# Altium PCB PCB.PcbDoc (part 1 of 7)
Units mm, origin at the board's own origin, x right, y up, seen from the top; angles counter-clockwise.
Board outline 243.2 x 142.8 mm, 4 copper layers (Top Layer, Layer 1, Layer 2, Bottom Layer), stack 0.603 mm thick; 451 components, 380 nets, 2276 pads, 1520 vias.
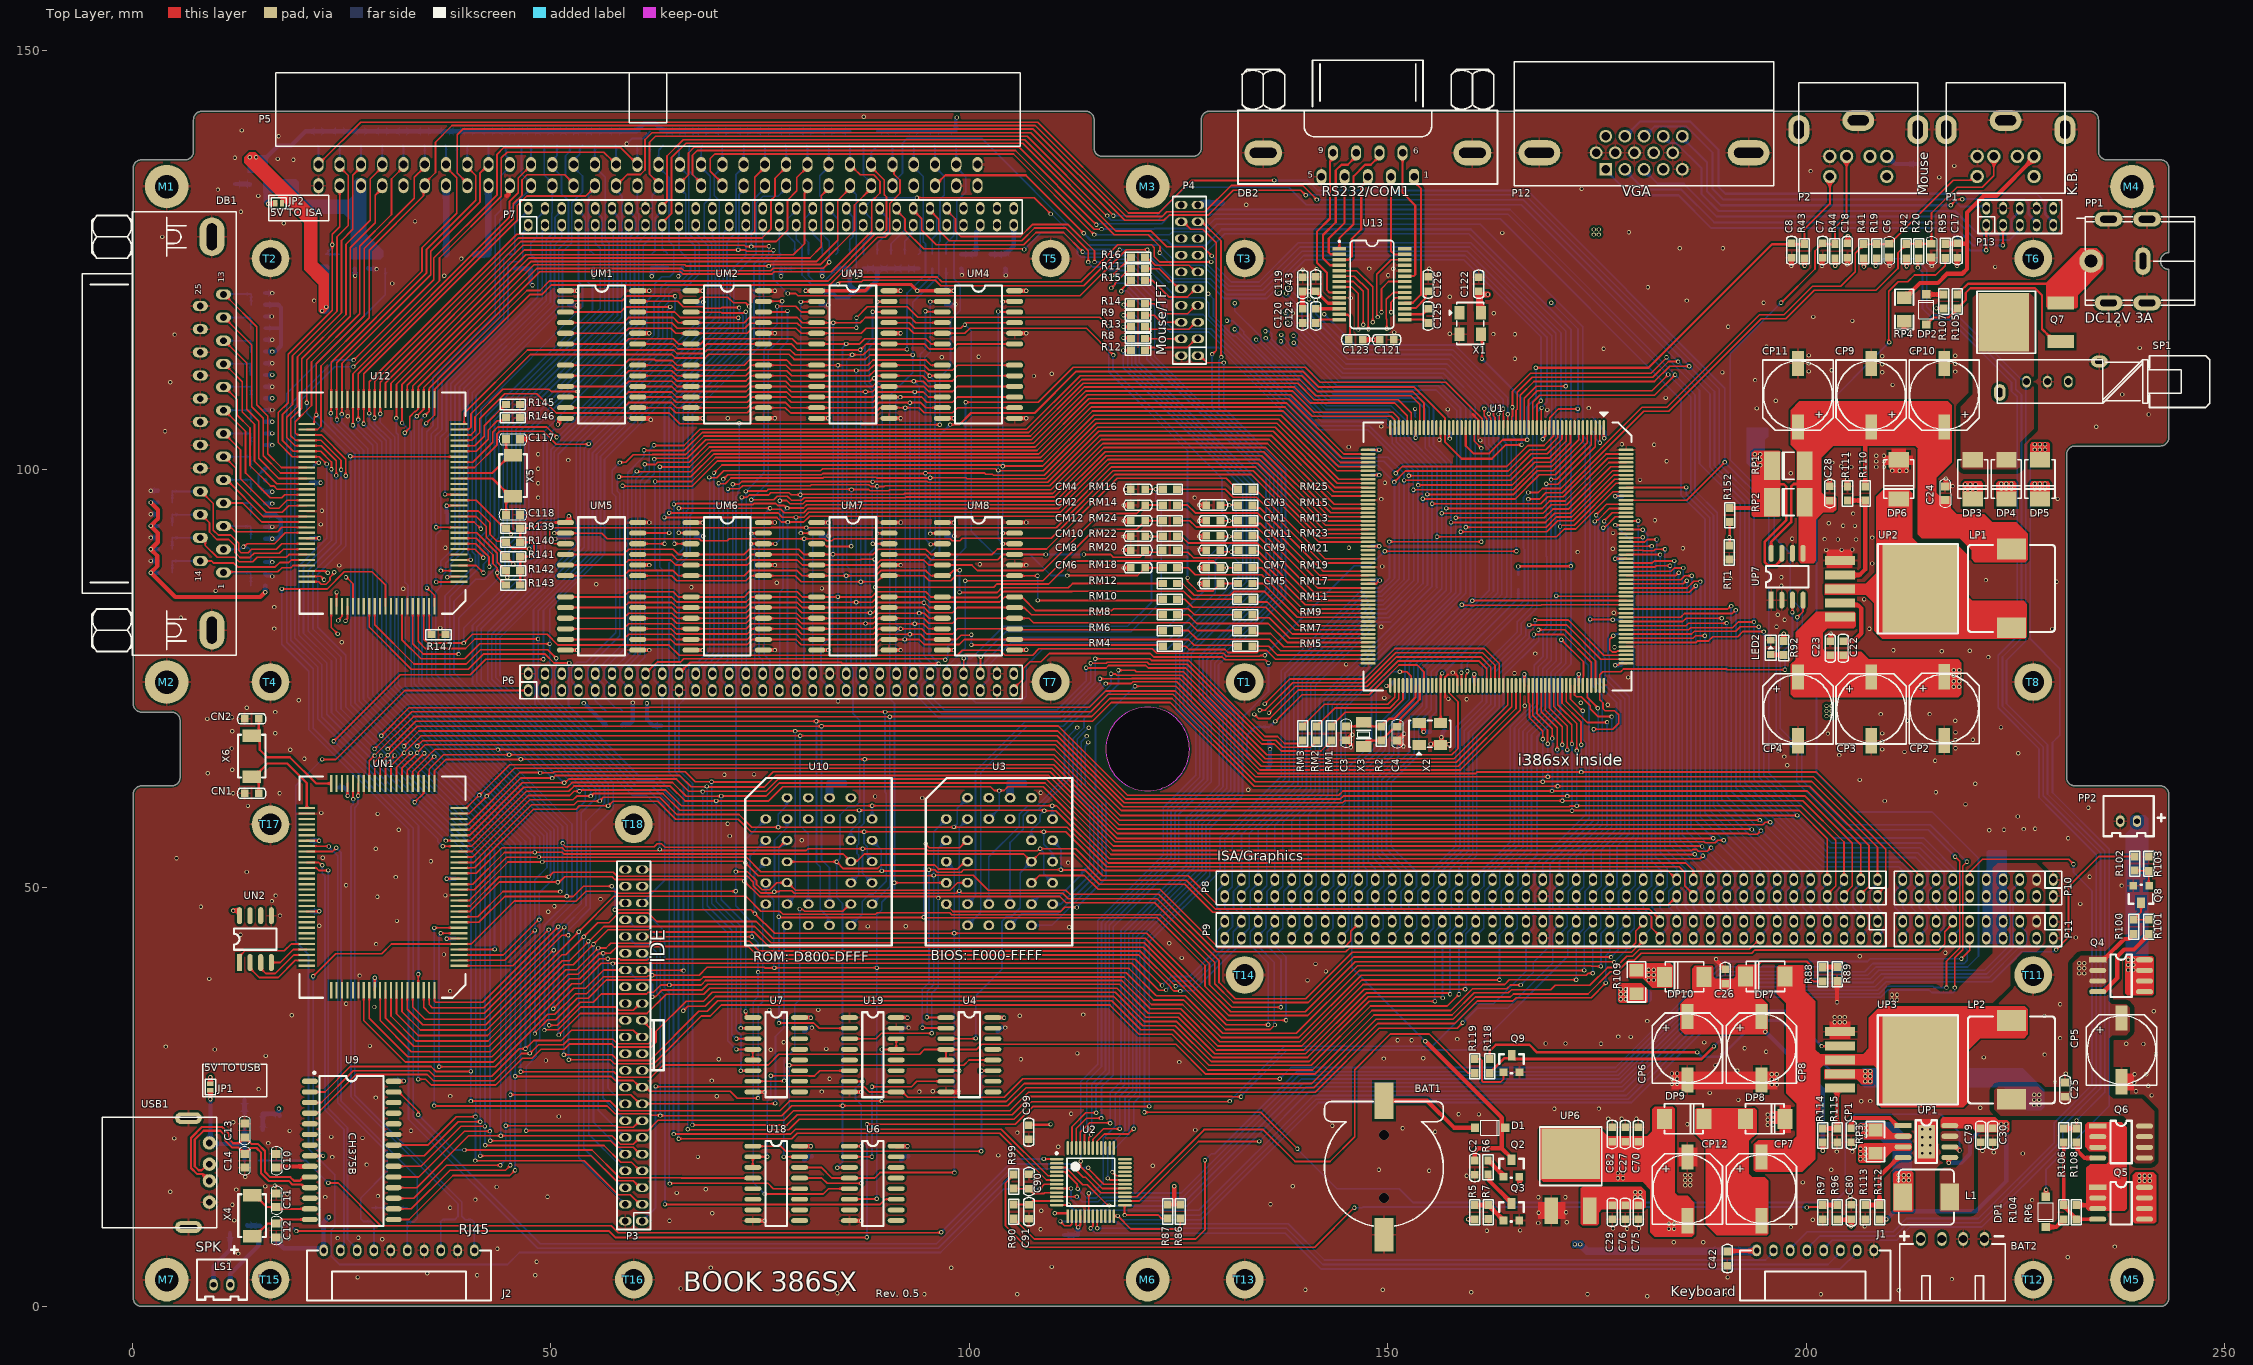
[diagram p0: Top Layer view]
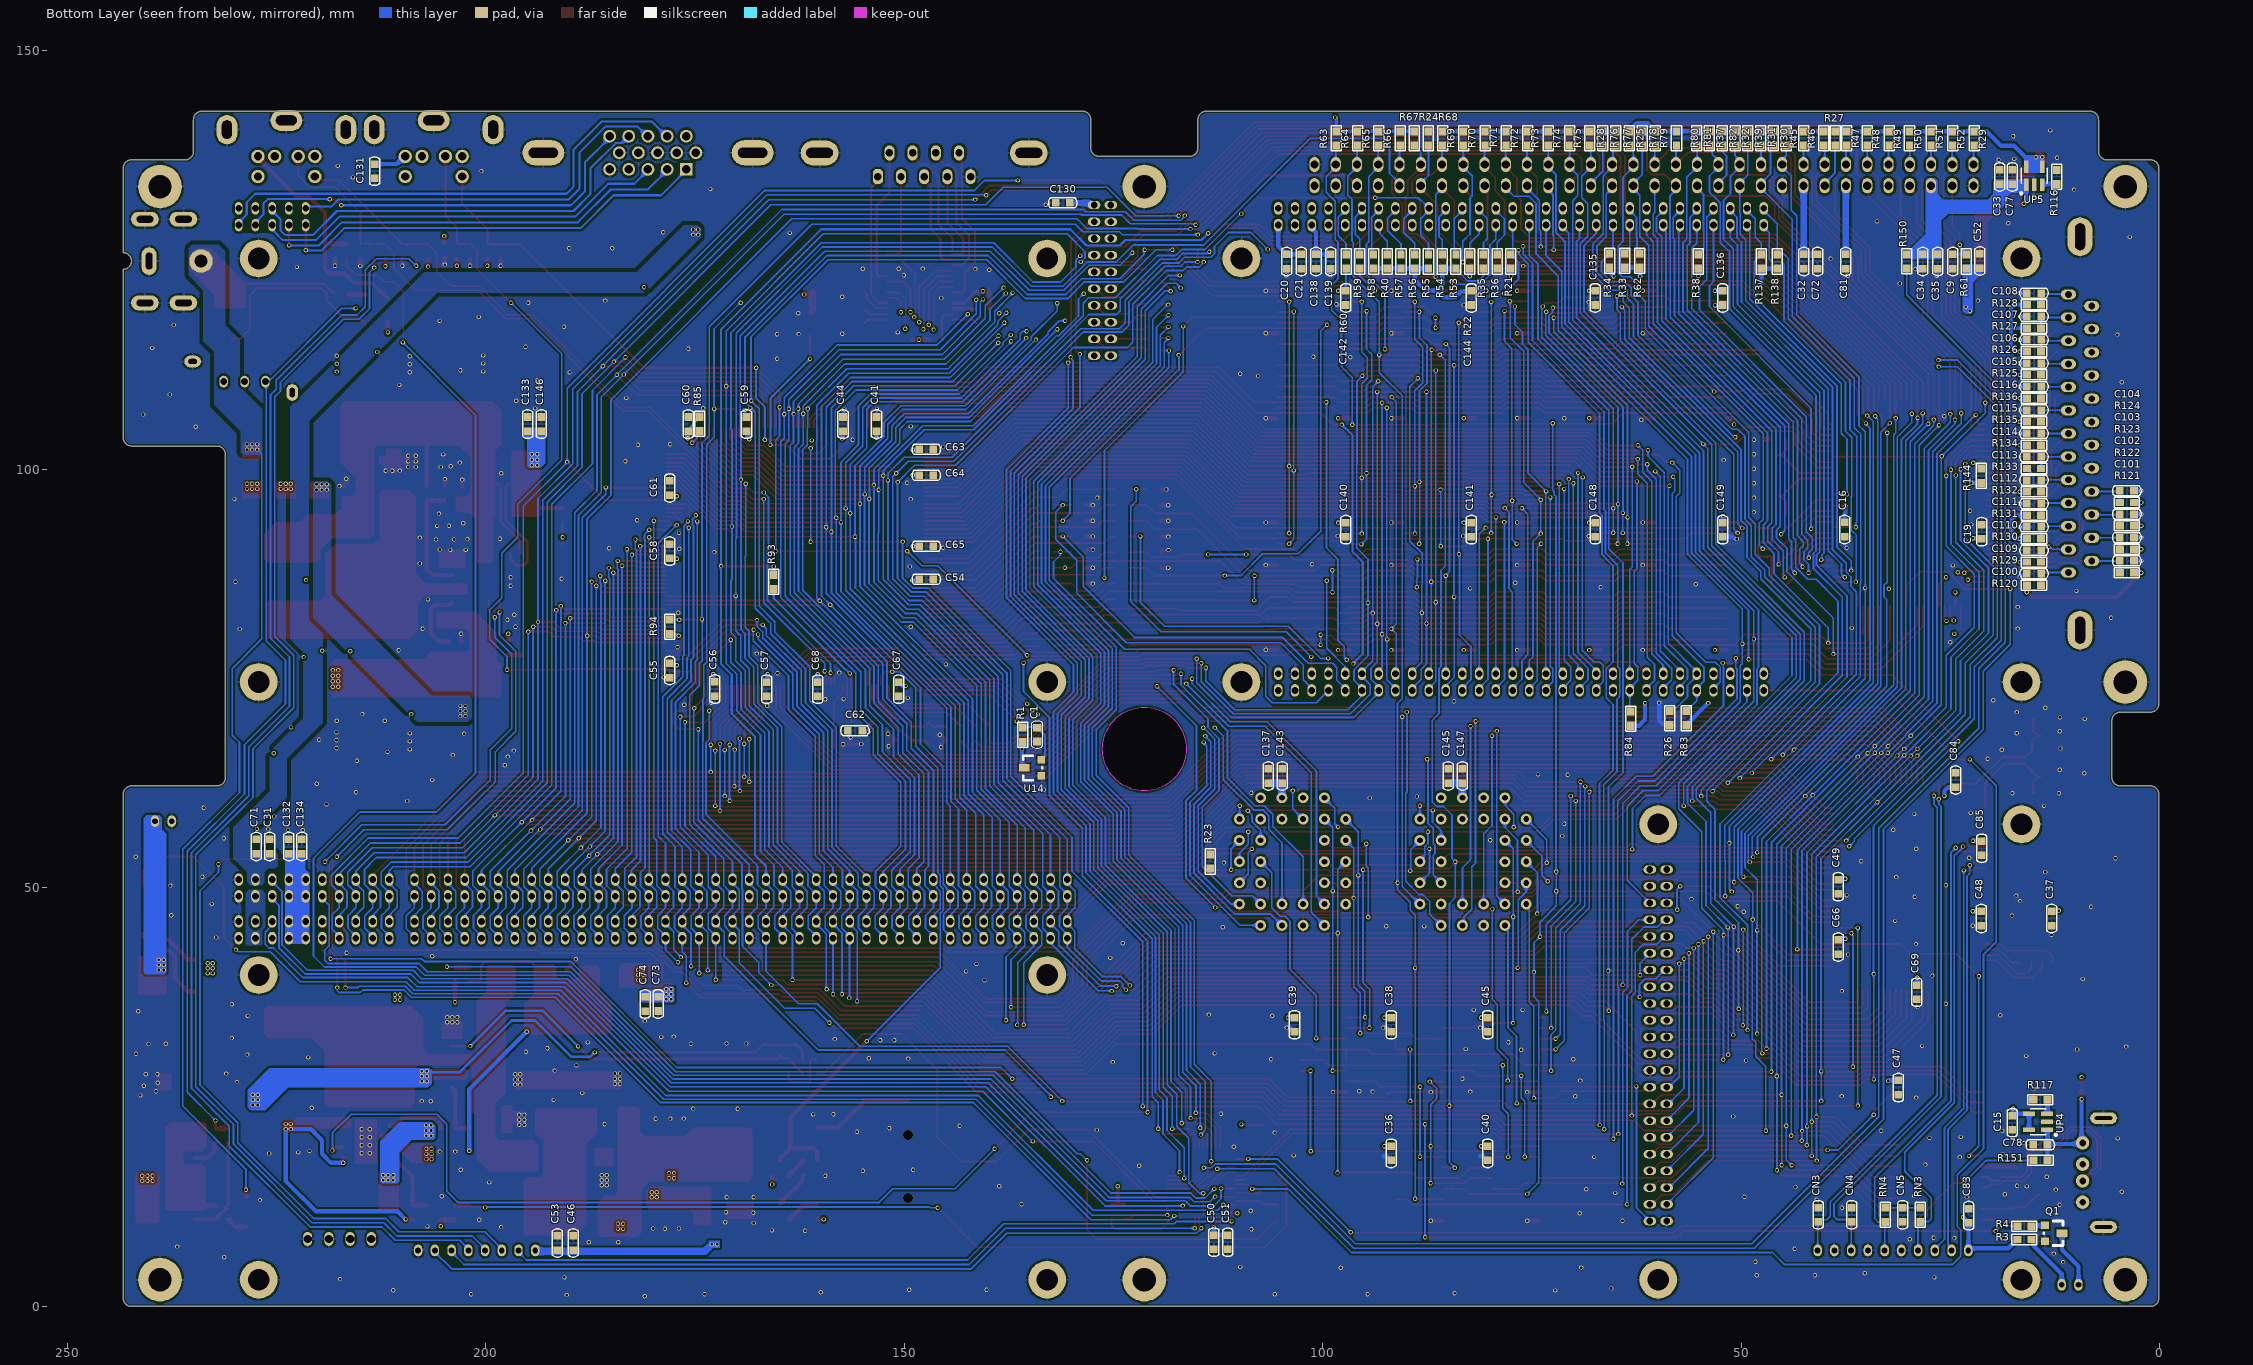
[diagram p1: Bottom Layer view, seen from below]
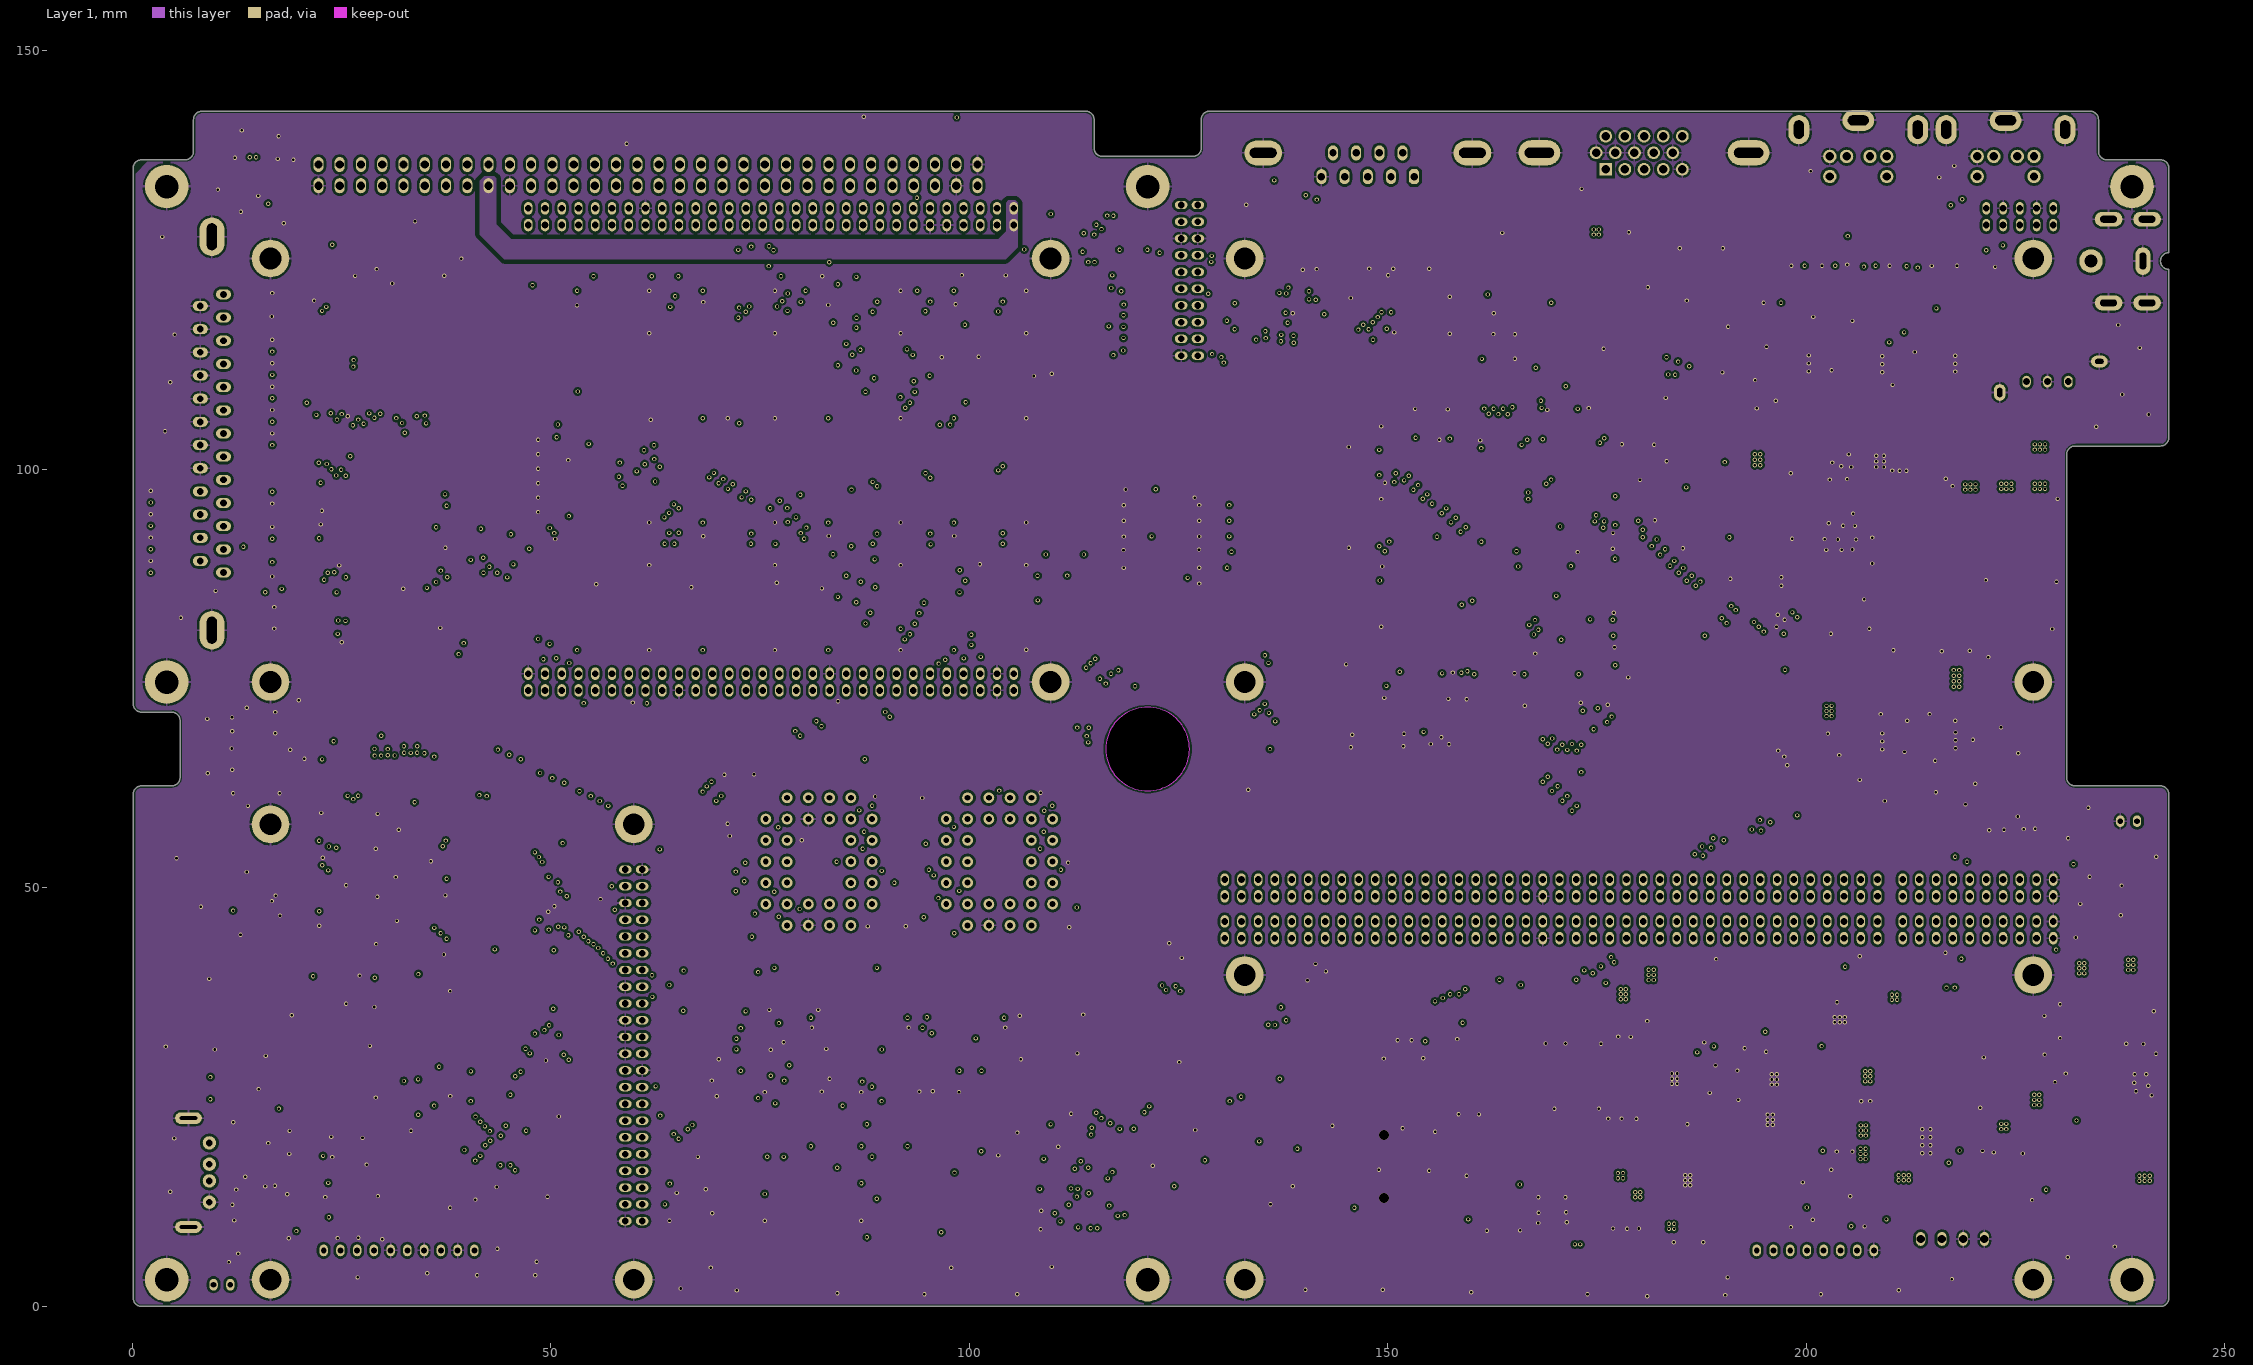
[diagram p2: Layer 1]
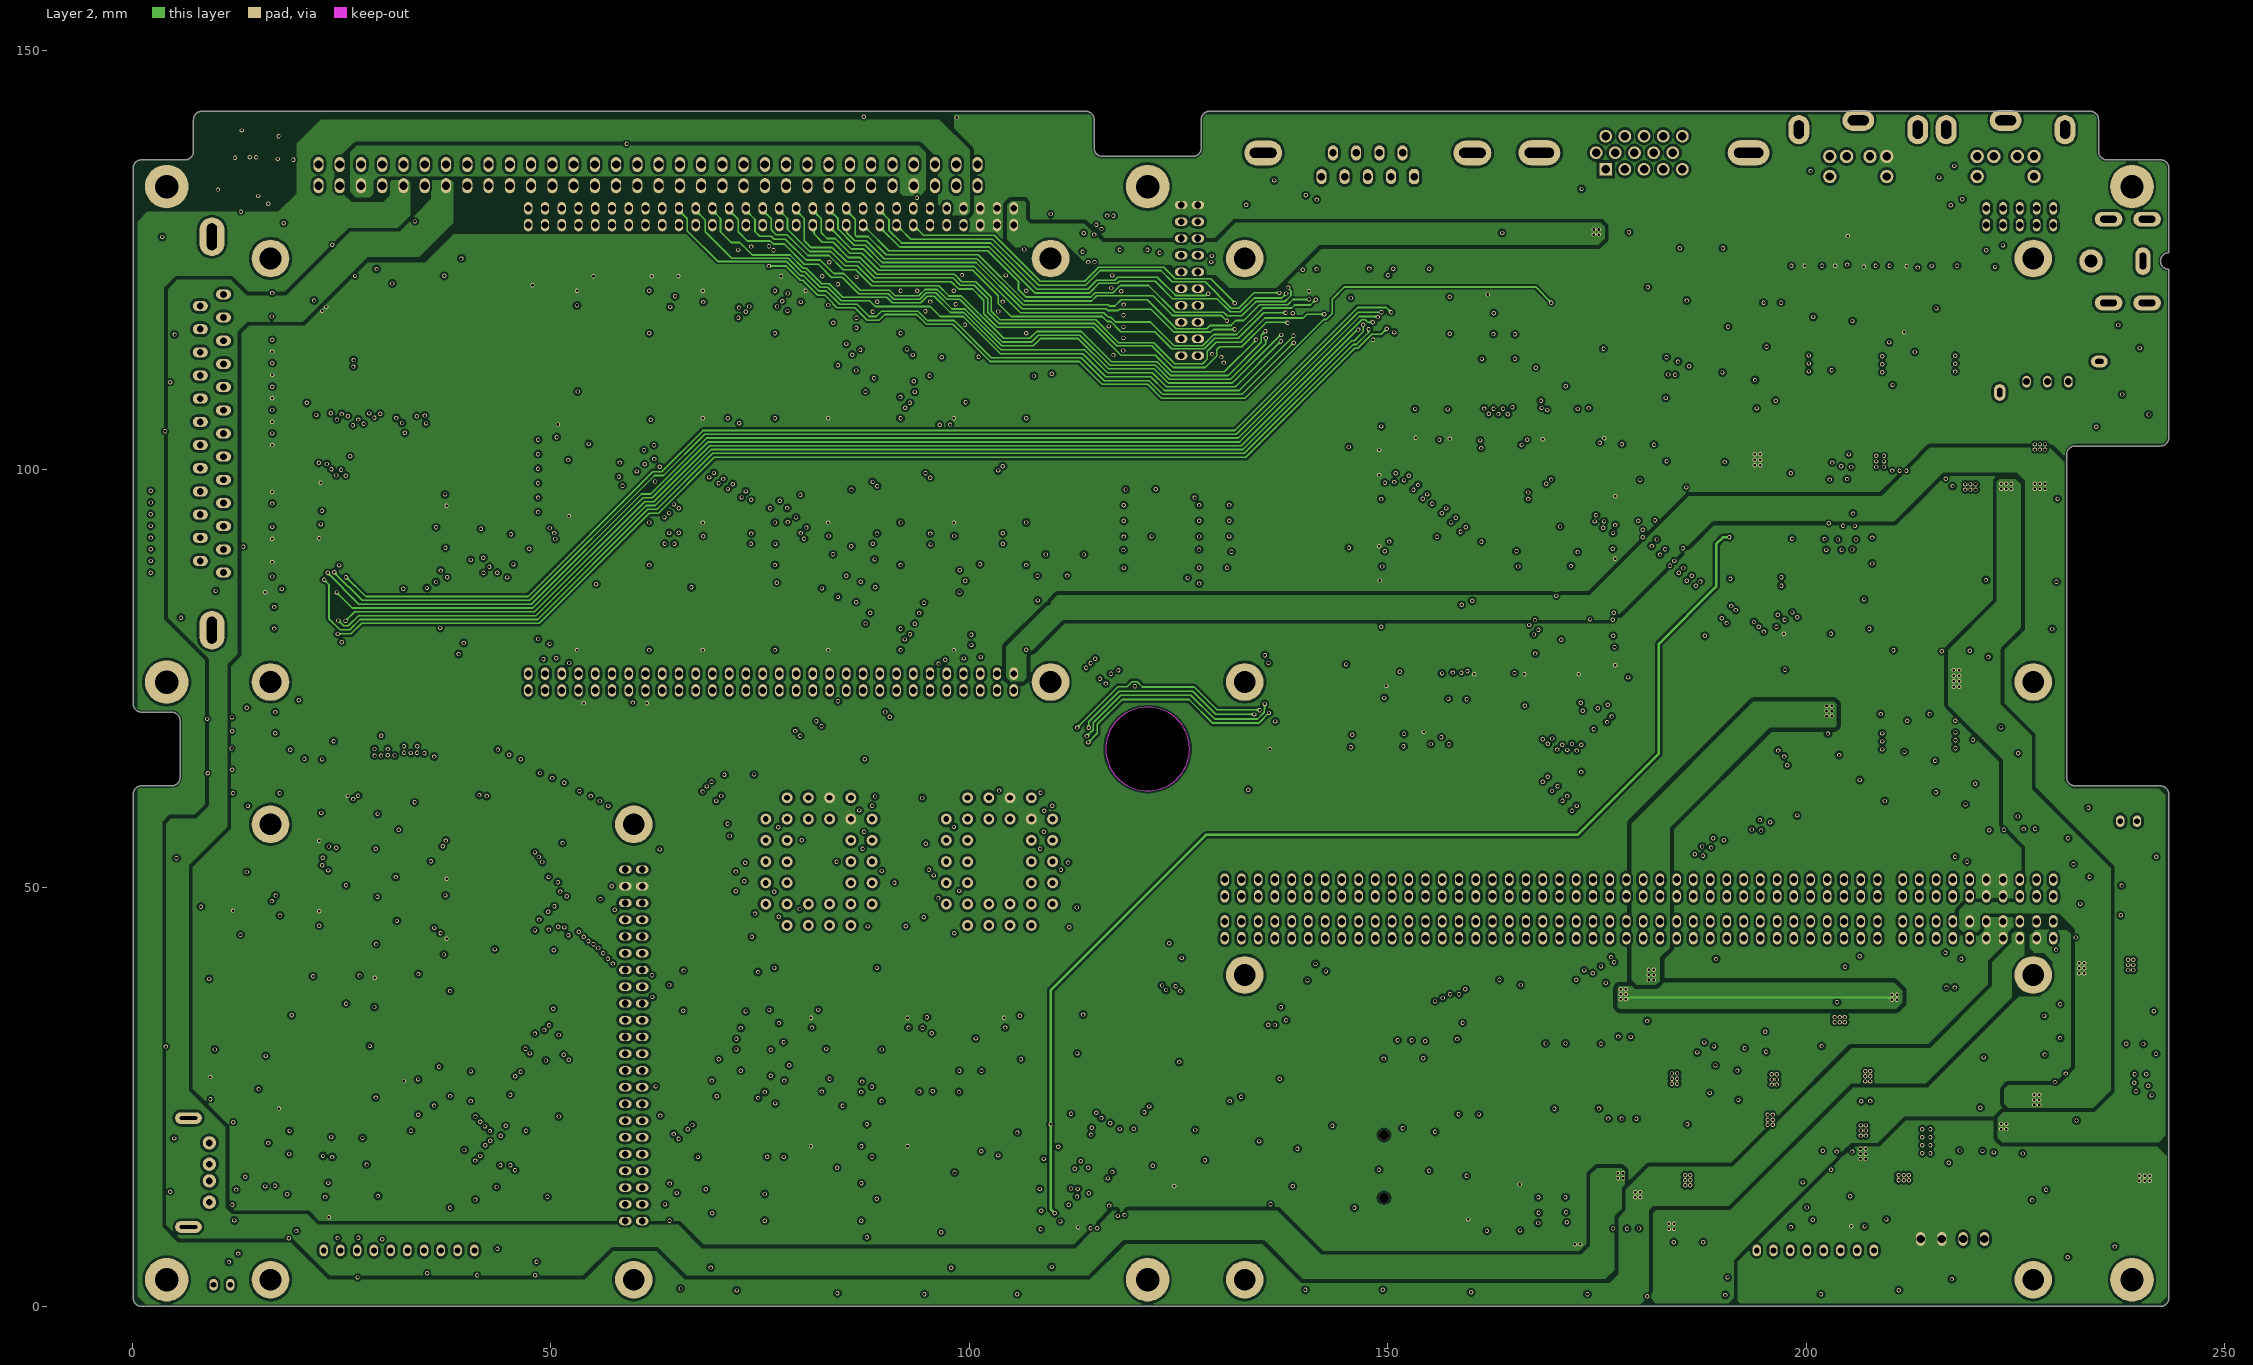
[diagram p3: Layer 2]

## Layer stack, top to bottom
Top Solder: solder mask 0.0102, Solder Resist, Dk 3.5
Top Layer: signal copper 0.0356
Dielectric 1: prepreg 0.0711, PP-006, Dk 4.1
Layer 1: signal copper 0.035
Dielectric1: dielectric 0.32, FR-4, Dk 4.8
Layer 2: signal copper 0.035
Dielectric 2: prepreg 0.0711, PP-006, Dk 4.1
Bottom Layer: signal copper 0.0356
Bottom Solder: solder mask 0.0102, Solder Resist, Dk 3.5

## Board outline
0.1,1 0.1,61.2 cw(c1.1,61.2) 1.1,62.2 4.7,62.2 ccw(c4.7,63.2) 5.7,63.2 5.7,70 ccw(c4.7,70) 4.7,71 1.1,71 cw(c1.1,72) 0.1,72 0.1,136 cw(c1.1,136) 1.1,137 6.3,137 ccw(c6.3,138) 7.3,138 7.3,141.8 cw(c8.3,141.8) 8.3,142.8 113.9,142.8 cw(c113.9,141.8) 114.9,141.8 114.9,138.4 ccw(c115.9,138.4) 115.9,137.4 126.7,137.4 ccw(c126.7,138.4) 127.7,138.4 127.7,141.8 cw(c128.7,141.8) 128.7,142.8 233.9,142.8 cw(c233.9,141.8) 234.9,141.8 234.9,138 ccw(c235.9,138) 235.9,137 242.3,137 cw(c242.3,136) 243.3,136 243.3,125.9 ccw(c243.3,124.9) 243.3,123.9 243.3,103.8 cw(c242.3,103.8) 242.3,102.8 232.1,102.8 ccw(c232.1,101.8) 231.1,101.8 231.1,63.2 ccw(c232.1,63.2) 232.1,62.2 242.3,62.2 cw(c242.3,61.2) 243.3,61.2 243.3,1 cw(c242.3,1) 242.3,0 1.1,0 cw(c1.1,1)
cut-out: 116.3,66.6 ccw(c121.3,66.6) 121.3,61.6 ccw(c121.3,66.6) 126.3,66.6 ccw(c121.3,66.6) 121.3,71.6 ccw(c121.3,66.6)

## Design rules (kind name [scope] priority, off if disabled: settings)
BoardOutlineClearance [All] p1: gap=0 ignorepadtopadclearanceinfootprint=FALSE except(0.254: Poly-OutlineEdge Poly-CavityEdge Poly-CutoutEdge Poly-SplitBarrior)
Clearance [All] p1: gap=0.203 ignorepadtopadclearanceinfootprint=FALSE except(0.178: Arc-Arc Arc-Track Track-Track SMDPad-SMDPad; 0.254: Arc-Fill Arc-Poly Arc-Region Track-Fill Track-Poly Track-Region SMDPad-Fill SMDPad-Poly SMDPad-Region Via-Fill Via-Poly Via-Region Fill-Fill Fill-Poly Fill-Region Poly-Region Region-Region; 0.305: THPad-Fill THPad-Poly THPad-Region; 0.508: Poly-Poly)
ComponentClearance [All] p1: gap=0 collisioncheckmode=3 verticalgap=0 showdistances=FALSE
HoleSize [All] p1: absolutevalues=TRUE maxlimit=25.4 minlimit=0.025 maxpercent=80.000 minpercent=20.000
HoleToHoleClearance [All] p1: gap=0 allowstackedmicrovias=TRUE
MinimumSolderMaskSliver [All] p1: minsoldermaskwidth=0
PlaneClearance [All] p1: clearance=0
PolygonConnect PolygonConnect_1 [InNet('GND')] p1: thpad.connectstyle=Relief thpad.reliefconductorwidth=0.254 thpad.reliefentries=4 thpad.polygonreliefangle="90 Angle" thpad.airgapwidth=0.254 smdpad.connectstyle=Relief smdpad.reliefconductorwidth=0.254 smdpad.reliefentries=4 smdpad.polygonreliefangle="90 Angle" smdpad.airgapwidth=0.254 via.connectstyle=Direct via.reliefconductorwidth=0.254 via.reliefentries=4 via.polygonreliefangle="90 Angle" via.airgapwidth=0.254
PolygonConnect [All] p2: connectstyle=Direct reliefconductorwidth=0.254 reliefentries=4 polygonreliefangle="90 Angle" airgapwidth=0.254
RoutingVias [All] p1: holewidth=0.305 width=0.508 viastyle="Through Hole" minholewidth=0.305 minwidth=0.508 maxholewidth=0.305 maxwidth=0.508
SilkToSilkClearance [All] p1: silktosilkclearance=0
SilkToSolderMaskClearance [IsPad] p1: minsilkscreentomaskgap=0 clearancetoexposedcopper=TRUE
SolderMaskExpansion [All] p1: expansion=0.102 istentingtop=FALSE
Width [All] p1: maxlimit=5.08 minlimit=0.203 preferedwidth=0.254 midlayer1_prefwidth=0.203 midlayer2_prefwidth=0.203 minimp=50.000000 maximp=50.000000 favimp=50.000000
23 further rules are at their usual default settings.

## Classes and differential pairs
component class P01_Power: BAT2 C15 C16 C19 C20 C21 C22 C23 C24 C25 C26 C27 C28 C29 C30 C31 C32 C33 C34 C35 C36 C37 C38 C39 C40 C41 C42 C43 C44 C45 C46 C47 C48 C49 C50 C51 C52 C53 C54 C55 C56 C57 C58 C59 C60 C61 C62 C63 C64 C65 C66 C67 C68 C69 C70 C71 C72 C73 C74 C75 C76 C77 C78 C79 C80 C81 C82 C83 C84 C85 C90 C91 C130 C131 C132 C133 C134 C135 C136 C137 C138 C139 C140 C141 C142 C143 C144 C145 C146 C147 C148 C149 CP1 CP2 CP3 CP4 CP5 CP6 CP7 CP8 CP9 CP10 CP11 CP12 DP1 DP2 DP3 DP4 DP5 DP6 DP7 DP8 DP9 DP10 JP1 JP2 L1 LP1 LP2 M1 M2 M3 M4 M5 M6 M7 PP1 PP2 Q4 Q5 Q6 Q7 Q8 Q9 R88 R89 R90 R96 R97 R99 R100 R101 R102 R103 R104 R105 R106 R107 R108 R109 R110 R111 R112 R113 R114 R115 R116 R117 R118 R119 R150 R151 RP1 RP2 RP3 RP6 SP1 T1 T2 T3 T4 T5 T6 T7 T8 T11 T12 T13 T14 T15 T16 T17 T18 UP1 UP2 UP3 UP4 UP5 UP6 UP7
component class P03_IO: C100 C101 C102 C103 C104 C105 C106 C107 C108 C109 C110 C111 C112 C113 C114 C115 C116 C117 C118 C119 C120 C121 C122 C123 C124 C125 C126 CN1 CN2 CN3 CN4 CN5 DB1 DB2 J2 R120 R121 R122 R123 R124 R125 R126 R127 R128 R129 R130 R131 R132 R133 R134 R135 R136 R137 R138 R139 R140 R141 R142 R143 R144 R145 R146 R147 RN3 RN4 U12 U13 UN1 UN2 X5 X6
component class P02_CPU: BAT1 C1 C2 C3 C4 C5 C6 C7 C8 C9 C10 C11 C12 C13 C14 C17 C18 C99 CM1 CM2 CM3 CM4 CM5 CM6 CM7 CM8 CM9 CM10 CM11 CM12 D1 F J1 LED2 LS1 P1 P2 P3 P4 P5 P6 P7 P8 P9 P10 P11 P12 P13 Q1 Q2 Q3 R1 R2 R3 R4 R5 R6 R7 R8 R9 R11 R12 R13 R14 R15 R16 R19 R20 R21 R22 R23 R24 R25 R26 R27 R28 R29 R30 R31 R32 R33 R34 R35 R36 R37 R38 R39 R40 R41 R42 R43 R44 R45 R46 R47 R48 R49 R50 R51 R52 R53 R54 R55 R56 R57 R58 R59 R60 R61 R62 R63 R64 R65 R66 R67 R68 R69 R70 R71 R72 R73 R74 R75 R76 R77 R78 R79 R80 R81 R82 R83 R84 R85 R86 R87 R92 R93 R94 R95 R152 RM1 RM2 RM3 RM4 RM5 RM6 RM7 RM8 RM9 RM10 RM11 RM12 RM13 RM14 RM15 RM16 RM17 RM18 RM19 RM20 RM21 RM22 RM23 RM24 RM25 RP4 RT1 U1 U2 U3 U4 U6 U7 U9 U10 U14 U18 U19 UM1 UM2 UM3 UM4 UM5 UM6 UM7 UM8 USB1 X1 X2 X3 X4

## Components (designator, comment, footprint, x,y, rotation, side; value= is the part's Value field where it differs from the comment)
BAT1 "BATTERY" BAT1220 149.53,8.585 r90 top
BAT2 "CON4" XH2.54A-4 221.271,8.067 r180 top locked
C1 "10uf" C0603#1 134.099,67.499 r90 bottom
C2 "10uf" C0603#2 160.387,17.44 r270 top
C3 "10pf" C0603#1 145.013,69.305 r270 top
C4 "10pf" C0603#1 151.113,67.605 r90 top
C5 "47pf" C0603#1 214.946,126.965 r270 top
C6 "47pf" C0603#1 209.917,126.965 r270 top
C7 "47pf" C0603#2 201.941,127.016 r270 top
C8 "47pf" C0603#2 198.233,127.016 r270 top
C9 "47pf" C0603#2 24.7,125.7 r270 bottom
C10 "0.1uf" C0603#1 17.2,16.583 r90 top
C11 "20pf" C0603#1 17.206,13.516 r270 top
C12 "20pf" C0603#1 17.2,8.25 r90 top
C13 "47pf" C0603#1 13.4,20.2 r90 top
C14 "47pf" C0603#1 13.406,18.233 r270 top
C15 "0.1uf" C0603#2 17.6,22.8 r270 bottom
C16 "0.1uf" C0603#2 37.643,93.675 r270 bottom
C17 "10uf" C0603#2 218.045,127.016 r270 top
C18 "10uf" C0603#2 204.888,127.016 r270 top
C19 "0.1uf" C0603#2 21.271,91.71 r90 bottom
C20 "0.1uf" C0603#2 104.3,125.7 r270 bottom
C21 "10uf" C0603#2 102.545,125.7 r270 bottom
C22 "1uf" C0603#2 204.38,77.79 r90 top
C23 "1uf" C0603#2 202.856,77.79 r90 top
C24 "1uf" C0603#1 216.572,96.332 r90 top
C25 "1uf" C0603#2 230.897,25.06 r90 top
C26 "1uf" C0603#2 190.308,38.573 r90 top
C27 "10uf" C0603#2 178.348,19.7 r90 top
C28 "1uf" C0603#2 202.805,96.282 r90 top
C29 "0.1uf" C0603#2 176.795,12.106 r270 top
C30 "0.1uf" C0603#2 222.287,21.301 r270 top
C31 "0.1uf" C0603#2 225.8,54.1 r90 bottom
C32 "0.1uf" C0603#2 42.5,125.7 r270 bottom
C33 "10uf" C0603#2 19.1,135.8 r270 bottom
C34 "0.1uf" C0603#2 28.3,124 r90 bottom
C35 "10uf" C0603#2 26.5,124 r90 bottom
C36 "0.1uf" C0603#2 91.817,19.142 r270 bottom
C37 "0.1uf" C0603#2 12.9,47.2 r270 bottom
C38 "0.1uf" C0603#2 91.817,34.509 r270 bottom
C39 "10uf" C0603#2 103.359,34.509 r270 bottom
C40 "0.1uf" C0603#2 80.275,19.142 r270 bottom
C41 "10uf" C0603#2 153.3,104.567 r90 bottom
C42 "10uf" C0603#2 190.562,6.569 r270 top
C43 "0.1uf" C0603#2 141.4,121.3 r90 top
C44 "0.1uf" C0603#2 157.3,104.567 r90 bottom
C45 "0.1uf" C0603#2 80.275,34.509 r270 bottom
C46 "10uf" C0603#2 189.535,6.731 r90 bottom
C47 "0.1uf" C0603#2 31.2,27 r270 bottom
C48 "0.1uf" C0603#2 21.3,47.2 r270 bottom
C49 "0.1uf" C0603#2 38.4,51 r270 bottom
C50 "10uf" C0603#2 112.979,8.533 r270 bottom
C51 "0.1uf" C0603#2 111.328,8.533 r270 bottom
C52 "0.1uf" C0603#2 21.463,124.055 r90 bottom
C53 "0.1uf" C0603#2 191.414,6.731 r90 bottom
C54 "0.1uf" C0603#2 148.2,86.858 r180 bottom
C55 "0.1uf" C0603#2 178,76.838 r270 bottom
C56 "0.1uf" C0603#2 172.604,74.614 r270 bottom
C57 "0.1uf" C0603#2 166.431,74.6 r270 bottom
C58 "0.1uf" C0603#2 178,89.392 r90 bottom
C59 "0.1uf" C0603#2 168.831,104.567 r90 bottom
C60 "0.1uf" C0603#2 175.8,104.567 r90 bottom
C61 "10uf" C0603#2 178,96.946 r90 bottom
C62 "0.1uf" C0603#2 155.027,68.799 r0 bottom
C63 "10uf" C0603#2 148.2,102.4 r180 bottom
C64 "0.1uf" C0603#2 148.2,99.3 r180 bottom
C65 "0.1uf" C0603#2 148.2,90.8 r180 bottom
C66 "0.1uf" C0603#2 38.4,43.8 r270 bottom
C67 "0.1uf" C0603#2 150.659,74.6 r270 bottom
C68 "0.1uf" C0603#2 160.3,74.6 r270 bottom
C69 "0.1uf" C0603#2 29,38.4 r270 bottom
C70 "10uf" C0603#2 179.9,19.7 r90 top
C71 "10uf" C0603#2 227.4,54.1 r90 bottom
C72 "10uf" C0603#2 40.869,125.7 r270 bottom
C73 "10uf" C0603#2 179.4,37 r270 bottom
C74 "0.1uf" C0603#2 180.939,36.98 r270 bottom
C75 "10uf" C0603#2 179.9,12.106 r270 top
C76 "10uf" C0603#2 178.348,12.106 r270 top
C77 "10uf" C0603#2 17.6,135.8 r270 bottom
C78 "10uf" C0603#2 15.1,19.3 r180 bottom
C79 "10uf" C0603#2 220.813,21.301 r270 top
C80 "10uf" C0603#2 205.359,10.43 r90 top
C81 "0.1uf" C0603#2 37.5,125.7 r270 bottom
C82 "0.1uf" C0603#2 176.795,19.7 r90 top
C83 "10uf" C0603#2 22.8,10 r90 bottom
C84 "0.1uf" C0603#2 24.359,62.052 r90 bottom
C85 "0.1uf" C0603#2 21.246,55.589 r270 bottom
C90 "0.1uf" C0603#2 107.121,14.076 r90 top
C91 "0.1uf" C0603#2 107.121,12.176 r270 top
C99 "0.1uf" C0603#2 107.086,21.666 r270 top
C100 "180pf" C0603#2 14.159,87.544 r0 bottom
C101 "180pf" C0603#2 4.761,89.068 r180 bottom
C102 "180pf" C0603#2 4.761,91.862 r180 bottom
C103 "180pf" C0603#2 4.761,94.656 r180 bottom
C104 "180pf" C0603#2 4.761,97.45 r180 bottom
C105 "180pf" C0603#2 14.159,112.69 r0 bottom
C106 "180pf" C0603#2 14.159,115.484 r0 bottom
C107 "180pf" C0603#2 14.159,118.278 r0 bottom
C108 "180pf" C0603#2 14.159,121.072 r0 bottom
C109 "180pf" C0603#2 14.159,90.338 r0 bottom
C110 "180pf" C0603#2 14.159,93.132 r0 bottom
C111 "180pf" C0603#2 14.159,95.926 r0 bottom
C112 "180pf" C0603#2 14.159,98.72 r0 bottom
C113 "180pf" C0603#2 14.159,101.514 r0 bottom
C114 "180pf" C0603#2 14.159,104.308 r0 bottom
C115 "180pf" C0603#2 14.159,107.102 r0 bottom
C116 "180pf" C0603#2 14.159,109.896 r0 bottom
C117 "20pf" C0603#1 46.3,103.6 r180 top
C118 "20pf" C0603#1 46.3,94.605 r180 top
C119 "10uf" C0603#2 139.816,121.263 r90 top
C120 "10uf" C0603#2 139.8,119.2 r270 top
C121 "10uf" C0603#2 149,115.5 r0 top
C122 "0.1uf" C0603#2 160.858,121.285 r90 top
C123 "0.1uf" C0603#2 147,115.5 r180 top
C124 "0.1uf" C0603#2 141.4,119.2 r270 top
C125 "0.1uf" C0603#2 154.8,119.2 r270 top
C126 "0.1uf" C0603#2 154.8,121.3 r90 top
C130 "0.1uf" C0603#2 130.186,131.842 r0 bottom
C131 "0.1uf" C0603#2 213.27,136.488 r270 bottom
C132 "0.1uf" C0603#2 223.5,54.1 r90 bottom
C133 "10uf" C0603#2 194.985,104.567 r90 bottom
C134 "10uf" C0603#2 221.938,54.1 r90 bottom
C135 "0.1uf" C0603#2 67.437,121.35 r270 bottom
C136 "0.1uf" C0603#2 52.2,121.35 r270 bottom
C137 "0.1uf" C0603#2 106.488,62.525 r90 bottom
C138 "10uf" C0603#2 100.79,125.7 r270 bottom
C139 "0.1uf" C0603#2 99.035,125.7 r270 bottom
C140 "0.1uf" C0603#2 97.225,93.659 r270 bottom
C141 "0.1uf" C0603#2 82.217,93.659 r270 bottom
C142 "0.1uf" C0603#2 97.225,121.35 r270 bottom
C143 "10uf" C0603#2 104.831,62.525 r90 bottom
C144 "0.1uf" C0603#2 82.217,121.35 r270 bottom
C145 "10uf" C0603#2 85,62.525 r90 bottom
C146 "0.1uf" C0603#2 193.331,104.567 r90 bottom
C147 "0.1uf" C0603#2 83.3,62.525 r90 bottom
C148 "0.1uf" C0603#2 67.437,93.659 r270 bottom
C149 "0.1uf" C0603#2 52.2,93.659 r270 bottom
CM1 "47pf" C0603#2 130,93.877 r180 top
CM2 "47pf" C0603#2 121,95.751 r180 top
CM3 "47pf" C0603#2 130,95.752 r180 top
CM4 "47pf" C0603#2 121,97.627 r180 top
CM5 "47pf" C0603#2 130,86.377 r180 top
CM6 "47pf" C0603#2 121,88.248 r180 top
CM7 "47pf" C0603#2 130,88.252 r180 top
CM8 "47pf" C0603#2 120.98,90.348 r180 top
CM9 "47pf" C0603#2 129.972,90.348 r180 top
CM10 "47pf" C0603#2 121,92 r180 top
CM11 "47pf" C0603#2 130,92.078 r180 top
CM12 "47pf" C0603#2 121,93.875 r180 top
CN1 "20pf" C0603#2 15.1,61.3 r180 top
CN2 "20pf" C0603#2 15.1,70.2 r180 top
CN3 "180pf" C0603#2 40.8,10.1 r90 bottom
CN4 "180pf" C0603#2 36.8,10.1 r90 bottom
CN5 "10nf" C0603#2 30.7,11.8 r270 bottom
CP1 "470nf" C0603#2 205.37,19.601 r90 top
CP2 "25v 100uf" SMD-EC-F8 216.47,71.44 r270 top
CP3 "25v 100uf" SMD-EC-F8 207.732,71.39 r270 top
CP4 "25v 100uf" SMD-EC-F8 198.995,71.39 r270 top
CP5 "25v 100uf" SMD-EC-F8 237.654,30.648 r270 top
CP6 "25v 100uf" SMD-EC-F8 185.787,30.851 r270 top
CP7 "25v 100uf" SMD-EC-F8 194.626,14.036 r270 top
CP8 "25v 100uf" SMD-EC-F8 194.626,30.851 r270 top
CP9 "16v 220uf" SMD-EC-F8 207.732,108.88 r90 top
CP10 "16v 220uf" SMD-EC-F8 216.47,108.88 r90 top
CP11 "16v 220uf" SMD-EC-F8 198.995,108.88 r90 top
CP12 "25v 100uf" SMD-EC-F8 185.787,14.036 r270 top
D1 "MMBD4148A" SOD123 160.401,21.361 r0 top
DB1 "DB25" DB25母 12.4,77.8 r90 top locked
DB2 "DB9" DB9公头S 132.1,134.1 r0 top locked
DP1 "1N5819W" SOD123 228.6,13.1 r270 top
DP2 "1N5819W" SOD123 214.336,117.313 r90 top
DP3 "SMB" DO-214B(SMB) 219.874,101.158 r270 top
DP4 "SMB" DO-214B(SMB) 223.887,101.158 r270 top
DP5 "SMB" DO-214B(SMB) 227.9,101.158 r270 top
DP6 "SMB" DO-214B(SMB) 211.034,101.158 r270 top
DP7 "SMB" DO-214B(SMB) 197.421,39.436 r180 top
DP8 "SMB" DO-214B(SMB) 192.721,22.418 r0 top
DP9 "SMB" DO-214B(SMB) 183.044,22.418 r0 top
DP10 "SMB" DO-214B(SMB) 187.744,39.386 r180 top
J1 "CON8" PH-8B 208.063,6.696 r180 top locked
J2 "CON10" PH-10B 40.854,6.696 r180 top locked
JP1 "CON2" JP2 9.322,26.619 r270 top
JP2 "CON2" JP2 17.882,131.801 r180 top
L1 "4.7uH" L0630 211.034,9.769 r0 top
LED2 "RED" LED0603 195.744,77.892 r90 top
LP1 "47uh" L1010 224.496,90.49 r270 top
LP2 "47uh" L1010 224.496,34.153 r270 top
LS1 "Speaker" PH-2 9.7,2.6 r0 top
M1 "CON1" M2.8D5.2 4.1,133.8 r0 top locked
M2 "CON1" M2.8D5.2 4.1,74.6 r0 top locked
M3 "CON1" M2.8D5.2 121.3,133.8 r0 top locked
M4 "CON1" M2.8D5.2 238.9,133.8 r0 top locked
M5 "CON1" M2.8D5.2 238.9,3.2 r0 top locked
M6 "CON1" M2.8D5.2 121.3,3.2 r0 top locked
M7 "CON1" M2.8D5.2 4.1,3.2 r0 top locked
P1 "KEYBOARD" PS2 216.7,133 r270 top locked
P2 "MOUSE" PS2 199.1,133 r270 top locked
P3 "CON2x22" PH2x22 60.9,10.2 r90 top
P4 "CON2x10" PH2x10 127.3,113.6 r90 top locked
P5 "CON2x32" IDC-2X32(2.54)B 61.6,138.6 r90 top locked
P6 "CON2x30" PH2x30 47.3,73.6 r0 top locked
P7 "CON2x30" PH2x30 47.3,129.2 r0 top locked
P8 "CON40x2" PH2x40 208.5,51 r180 top locked
P9 "CON40x2" PH2x40 208.5,46 r180 top locked
P10 "CON2x10" PH2x10 229.5,51 r180 top locked
P11 "CON2x10" PH2x10 229.5,46 r180 top locked
P12 "VGA" "VGA 15-S" 165.1,133.9 r0 top locked
P13 "CON2x5" PH2x5 221.5,129.2 r0 top locked
PP1 "DCIN" DC5.5-DC007 233.3,130.2 r270 top locked
PP2 "CON2" PH-2 237.501,57.978 r0 top
Q1 "MMBT3904(1AM)" SOT23 12.684,8.748 r270 bottom
Q2 "MMBT3906" SOT23 164.756,16.526 r0 top
Q3 "MMBT3904(1AM)" SOT23 164.756,11.293 r0 top
Q4 "AO4453" SO-8 234.809,41.418 r0 top
Q5 "AO4453" SO-8 234.809,14.24 r0 top
Q6 "AO4453" SO-8 234.809,21.555 r0 top
Q7 "AOD403" TO-252-MOS 230.382,115.292 r90 top
Q8 "MMBT3904(1AM)" SOT23 239.99,49.241 r180 top
Q9 "MMBT3904(1AM)" SOT23 164.77,28.981 r0 top
R1 "1k" R0603 135.799,67.449 r90 bottom
R2 "20M" R0603 149.213,67.605 r90 top
R3 "33" R0603 15.3,8 r0 bottom
R4 "4.7k" R0603 17,9.6 r180 bottom
R5 "47k" R0603 160.387,12.106 r270 top
R6 "10k" R0603 161.962,15.764 r90 top
R7 "10k" R0603 162.012,10.43 r90 top
R8 "510" R0603 120.999,115.649 r180 top
R9 "510" R0603 120.999,118.424 r180 top
R11 "510" R0603 120.999,123.974 r180 top
R12 "510" R0603 120.999,114.262 r180 top
R13 "510" R0603 120.999,117.037 r180 top
R14 "510" R0603 120.999,119.812 r180 top
R15 "510" R0603 120.999,122.587 r180 top
R16 "510" R0603 120.999,125.362 r180 top
R19 "510" R0603 208.393,126.914 r270 top
R20 "510" R0603 213.422,126.914 r270 top
R21 "4.7k" R0603 77.5,124 r90 bottom
R22 "4.7k" R0603 82.425,124 r90 bottom
R23 "4.7k" R0603 113.448,54.014 r270 bottom
R24 "4.7k" R0603 87.353,140.4 r270 bottom
R25 "4.7k" R0603 61.825,140.4 r270 bottom
R26 "4.7K" R0603 58.507,71.136 r270 bottom
R27 "1k" R0603 38.772,138.7 r90 bottom
R28 "1k" R0603 66.519,138.7 r90 bottom
R29 "1k" R0603 22.16,138.7 r90 bottom
R30 "1k" R0603 44.614,138.7 r90 bottom
R31 "1k" R0603 46.141,138.7 r90 bottom
R32 "1k" R0603 49.196,138.7 r90 bottom
R33 "1k" R0603 63.913,125.802 r270 bottom
R34 "1k" R0603 65.721,125.802 r270 bottom
R35 "1k" R0603 80.783,125.7 r270 bottom
R36 "1k" R0603 79.142,125.7 r270 bottom
R37 "1k" R0603 52.252,138.7 r90 bottom
R38 "1k" R0603 55.1,125.7 r270 bottom
R39 "1k" R0603 47.669,138.7 r90 bottom
R40 "1k" R0603 92.275,125.7 r270 bottom
R41 "4.7k" R0603 206.869,126.914 r270 top
R42 "4.7k" R0603 211.949,126.914 r270 top
R43 "4.7k" R0603 199.757,126.914 r270 top
R44 "4.7k" R0603 203.414,126.914 r270 top
R45 "4.7k" R0603 42.531,138.7 r90 bottom
R46 "4.7k" R0603 40.143,138.7 r90 bottom
R47 "4.7k" R0603 37.4,138.7 r90 bottom
R48 "4.7k" R0603 34.911,138.7 r90 bottom
R49 "4.7k" R0603 32.32,138.7 r90 bottom
R50 "4.7k" R0603 29.882,138.7 r90 bottom
R51 "4.7k" R0603 27.308,138.7 r90 bottom
R52 "4.7k" R0603 24.734,138.7 r90 bottom
R53 "4.7k" R0603 84.067,125.7 r270 bottom
R54 "4.7k" R0603 85.708,125.7 r270 bottom
R55 "4.7k" R0603 87.35,125.7 r270 bottom
R56 "4.7k" R0603 88.992,125.7 r270 bottom
R57 "4.7k" R0603 90.633,125.7 r270 bottom
R58 "4.7k" R0603 93.917,125.7 r270 bottom
R59 "4.7k" R0603 95.558,125.7 r270 bottom
R60 "4.7k" R0603 97.2,125.7 r270 bottom
R61 "4.7k" R0603 23.1,125.7 r270 bottom
R62 "4.7k" R0603 62.106,125.802 r270 bottom
R63 "4.7k" R0603 98.36,138.7 r90 bottom
R64 "4.7k" R0603 95.82,138.7 r90 bottom
R65 "4.7k" R0603 93.28,138.7 r90 bottom
R66 "4.7k" R0603 90.74,138.7 r90 bottom
R67 "4.7k" R0603 89.047,138.7 r90 bottom
R68 "4.7k" R0603 85.66,138.7 r90 bottom
R69 "4.7k" R0603 83.12,138.7 r90 bottom
R70 "4.7k" R0603 80.58,138.7 r90 bottom
R71 "4.7k" R0603 78.04,138.7 r90 bottom
R72 "4.7k" R0603 75.5,138.7 r90 bottom
R73 "4.7k" R0603 73.062,138.7 r90 bottom
R74 "4.7k" R0603 70.471,138.7 r90 bottom
R75 "4.7k" R0603 68.083,138.7 r90 bottom
R76 "4.7k" R0603 64.954,138.7 r90 bottom
R77 "4.7k" R0603 63.389,138.7 r90 bottom
R78 "4.7k" R0603 60.26,138.7 r90 bottom
R79 "4.7k" R0603 57.72,138.7 r90 bottom
R80 "4.7k" R0603 55.307,138.7 r90 bottom
R81 "4.7k" R0603 53.779,138.7 r90 bottom
R82 "4.7k" R0603 50.724,138.7 r90 bottom
R83 "4.7k" R0603 56.552,71.136 r270 bottom
R84 "4.7k" R0603 63.181,71.085 r270 bottom
R85 "4.7k" R0603 174.4,104.6 r90 bottom
R86 "4.7k" R0603 125.197,10.49 r90 top
R87 "4.7k" R0603 123.723,10.49 r90 top
R88 "10k" R0603 201.967,38.827 r90 top
R89 "5k" R0603 203.662,40.554 r270 top
R90 "10k" R0603 105.321,12.176 r270 top
R92 "10k" R0603 197.318,79.518 r270 top
R93 "33" R0603 165.568,85.717 r90 bottom
R94 "33" R0603 177.989,80.356 r90 bottom
R95 "10k" R0603 216.572,126.965 r270 top
R96 "10k" R0603 203.662,10.406 r90 top
R97 "10k" R0603 201.967,12.106 r270 top
R99 "10k" R0603 105.321,14.076 r90 top
R100 "4.7k" R0603 239.127,44.516 r90 top
R101 "10k" R0603 240.905,44.516 r90 top
R102 "1k" R0603 239.228,53.762 r270 top
R103 "10k" R0603 240.905,52.035 r90 top
R104 "100R" R0603 230.745,10.406 r90 top
R105 "47k" R0603 218.045,120.92 r270 top
R106 "4.7k" R0603 230.745,19.574 r90 top
R107 "4.7k" R0603 216.419,120.92 r270 top
R108 "4.7k" R0603 232.218,19.574 r90 top
R109 "0R" 1206 179.691,40.173 r270 top
R110 "10k" R0603 207.021,96.282 r90 top
R111 "3.3k" R0603 204.912,96.282 r90 top
R112 "100k" R0603 208.748,10.406 r90 top
R113 "100k" R0603 207.053,10.406 r90 top
R114 "8.87k" R0603 201.967,19.574 r90 top
R115 "1k" R0603 203.662,19.574 r90 top
R116 "6.8k" R0603 12.3,135.8 r270 bottom
R117 "10k" R0603 15.1,24.7 r180 bottom
R118 "4.7k" R0603 162.154,27.864 r90 top
R119 "4.7k" R0603 160.376,27.864 r90 top
R120 "1k" R0603 14.159,86.147 r0 bottom
R121 "1k" R0603 4.761,87.671 r180 bottom
R122 "1k" R0603 4.761,90.465 r180 bottom
R123 "1k" R0603 4.761,93.259 r180 bottom
R124 "1k" R0603 4.761,96.053 r180 bottom
R125 "1k" R0603 14.159,111.293 r0 bottom
R126 "1k" R0603 14.159,114.087 r0 bottom
R127 "1k" R0603 14.159,116.881 r0 bottom
R128 "1k" R0603 14.159,119.675 r0 bottom
R129 "1k" R0603 14.159,88.941 r0 bottom
R130 "1k" R0603 14.159,91.735 r0 bottom
R131 "1k" R0603 14.159,94.529 r0 bottom
R132 "1k" R0603 14.159,97.323 r0 bottom
R133 "1k" R0603 14.159,100.117 r0 bottom
R134 "1k" R0603 14.159,102.911 r0 bottom
R135 "1k" R0603 14.159,105.705 r0 bottom
R136 "1k" R0603 14.159,108.499 r0 bottom
R137 "1k" R0603 47.576,125.7 r270 bottom
R138 "1k" R0603 45.676,125.7 r270 bottom
R139 "1k" R0603 44.641,92.995 r0 top
R140 "1k" R0603 44.641,91.296 r0 top
R141 "1k" R0603 44.641,89.597 r0 top
R142 "1k" R0603 44.641,87.897 r0 top
R143 "1k" R0603 44.641,86.198 r0 top
R144 "1k" R0603 21.3,100.1 r270 bottom
R145 "1k" R0603 44.615,107.76 r0 top
R146 "1k" R0603 44.615,106.16 r0 top
R147 "1k" R0603 35.725,80.28 r0 top
R150 "1k" R0603 30.226,125.705 r270 bottom
R151 "1k" R0603 13.386,17.45 r0 bottom
R152 "10k" R0603 190.83,93.701 r90 top
RM1 "10" R0603 143.213,69.305 r270 top
RM2 "10" R0603 141.513,69.305 r270 top
RM3 "10" R0603 139.813,69.305 r270 top
RM4 "10" R0603 124.8,78.875 r180 top
RM5 "10" R0603 133.8,78.875 r180 top
RM6 "10" R0603 124.8,80.75 r180 top
RM7 "10" R0603 133.8,80.75 r180 top
RM8 "10" R0603 124.8,82.625 r180 top
RM9 "10" R0603 133.8,82.625 r180 top
RM10 "10" R0603 124.8,84.5 r180 top
RM11 "10" R0603 133.8,84.5 r180 top
RM12 "10" R0603 124.8,86.375 r180 top
RM13 "10" R0603 133.8,93.875 r180 top
RM14 "10" R0603 124.8,95.75 r180 top
RM15 "10" R0603 133.8,95.75 r180 top
RM16 "10" R0603 124.8,97.625 r180 top
RM17 "33" R0603 133.8,86.375 r180 top
RM18 "33" R0603 124.8,88.25 r180 top
RM19 "33" R0603 133.8,88.25 r180 top
RM20 "33" R0603 124.79,90.348 r180 top
RM21 "33" R0603 133.833,90.322 r180 top
RM22 "33" R0603 124.8,92 r180 top
RM23 "33" R0603 133.8,92.076 r180 top
RM24 "33" R0603 124.8,93.875 r180 top
RM25 "10" R0603 133.8,97.625 r180 top
RN3 "100" R0603 28.6,11.8 r270 bottom
RN4 "100" R0603 32.8,11.8 r270 bottom
RP1 "0.2R 1%" 1812 197.85,100.447 r0 top
RP2 "0.2R 1%" 1812 197.85,96.1 r0 top
RP3 "0.02" 1206 208.24,21.098 r270 top
RP4 "10R" 1206 211.695,120.513 r270 top
RP6 "47k" R0603 232.218,12.106 r270 top
RT1 "10k T" R0603 190.805,90.932 r270 top
SP1 "POWER" SW3 222.8,107.9 r0 top locked
T1 "CON1" M2.6 132.9,74.6 r0 top locked
T2 "CON1" M2.6 16.5,125.2 r0 top locked
T3 "CON1" M2.6 132.9,125.2 r0 top locked
T4 "CON1" M2.6 16.5,74.6 r0 top locked
T5 "CON1" M2.6 109.7,125.2 r0 top locked
T6 "CON1" M2.6 227.1,125.2 r0 top locked
T7 "CON1" M2.6 109.7,74.6 r0 top locked
T8 "CON1" M2.6 227.1,74.6 r0 top locked
T11 "CON1" M2.6 227.1,39.6 r0 top locked
T12 "CON1" M2.6 227.1,3.2 r0 top locked
T13 "CON1" M2.6 132.9,3.2 r0 top locked
T14 "CON1" M2.6 132.9,39.6 r0 top locked
T15 "CON1" M2.6 16.5,3.2 r0 top locked
T16 "CON1" M2.6 59.9,3.2 r0 top locked
T17 "CON1" M2.6 16.5,57.6 r0 top locked
T18 "CON1" M2.6 59.9,57.6 r0 top locked
U1 "M6117C" QFP208 175.805,104.994 r180 top locked
U2 "STC8G2K64S4-48PIN" LQFP48 114.506,14.853 r0 top
U3 "29C512_PLCC32" PLCC32P#1 104.862,58.232 r0 top locked
U4 "74LS138" SO-16 97.212,34.52 r0 top
U6 "74LS138" SO-16 85.67,19.153 r0 top
U7 "74LS138" SO-16 74.128,34.52 r0 top
U9 "CH375B" SOP-28 21.2,26.9 r270 top
U10 "29C512_PLCC32" PLCC32P#2 83.298,58.232 r0 top locked
U12 "M5113" PQFP100B 39.026,86.579 r90 top
U13 "MAX211" SSOP28 144.2,126.35 r0 top
U14 "MAX809" SOT-23 133.604,63.398 r90 bottom
U18 "74HC139" SO-16 74.128,19.153 r0 top
U19 "74HC139" SO-16 85.67,34.52 r0 top
UM1 "DRAM-SOJ24" SOJ-24-A 51.739,121.35 r0 top
UM2 "DRAM-SOJ24" SOJ-24-A 66.747,121.35 r0 top
UM3 "DRAM-SOJ24" SOJ-24-A 81.756,121.35 r0 top
UM4 "DRAM-SOJ24" SOJ-24-A 96.764,121.35 r0 top
UM5 "DRAM-SOJ24" SOJ-24-A 51.739,93.659 r0 top
UM6 "DRAM-SOJ24" SOJ-24-A 66.747,93.659 r0 top
UM7 "DRAM-SOJ24" SOJ-24-A 81.756,93.659 r0 top
UM8 "DRAM-SOJ24" SOJ-24-A 96.764,93.659 r0 top
UN1 "RTL8019AS" PQFP100B 39.026,40.7 r90 top
UN2 "93C46" SO-8 12.79,41.1 r90 top
UP1 "PW4203" "SO-8 A" 211.542,21.606 r0 top
UP2 "XL4016E1" TO-263(T) 204.024,89.119 r270 top
UP3 "XL6019" TO-263(T) 204.024,32.832 r270 top
UP4 "LPW5209AB5F" SOT23-5 13.437,21.123 r90 bottom
UP5 "LPW5209AB5F" SOT23-5 15.932,134.017 r180 bottom
UP6 "79M05" TO-252(DPAK) 169.531,11.446 r0 top
UP7 "INA219_SOP" SO-8 195.794,84.394 r90 top
USB1 "USB" USB-A-02 10.1,22.6 r180 top locked
X1 "5032-5V-80M" CRY-5032 158.242,119.939 r270 top
X2 "5032-5V-14.318M" CRY-5032 152.513,66.805 r0 top
X3 "3215-32768Hz" CRY3215A 147.113,69.805 r270 top
X4 "12M" 5032 12.649,13.408 r270 top
X5 "24M" 5032 47.128,96.709 r90 top
X6 "20M" 5032 12.6,68.3 r270 top

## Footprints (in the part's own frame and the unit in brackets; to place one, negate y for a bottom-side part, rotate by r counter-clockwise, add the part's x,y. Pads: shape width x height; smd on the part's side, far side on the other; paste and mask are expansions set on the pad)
1206 [mm]
  rect 1.524x1.7 smd: 1(0,0) 2(2.8,0)
  silkscreen extent -1,-1.1 3.8,1.1
1812 [mm] "Chip Capacitor; Body 4.5 x 3.2 mm (LxW typ)"
  rect 1.9x3.4 smd: 1(-1.95,0) 2(1.95,0)
  silkscreen extent -0.7,-1.6 0.7,1.6
5032 [mm]
  rect 1.5x2.2 smd: 1(0.108,1.651) 2(5.008,1.651)
  silkscreen extent 0,0 5.11,3.3
BAT1220 [mm]
  rect 4.4x2.3 smd: 1(16,0)
  rect 4x2.3 smd: 2(0,0)
  silkscreen extent 1.02,-7.1 15.9,7.1
C0603#1 [mil]
  rect 37.01x40 smd: 1(0,0)
  rect 37x40 smd: 2(64.98,0)
  silkscreen extent -34,-25 98,25
C0603#2 [mil]
  rect 35.43x35.43 smd: 1(0,0) 2(66.93,0)
  silkscreen extent -34,-24 100,24
CRY3215A [mm]
  rect 1.3x1.8 smd: 1(0,0) 2(2.9,0)
  silkscreen extent 0.95,-0.8 1.95,0.8
CRY-5032 [mm]
  rect 1.6x1.2 smd: 1(1.23,0.3) 2(3.77,0.3) 3(3.77,2.9) 4(1.23,2.9)
  silkscreen extent 0,-0.9 5,3.2
DB9公头S [mm]
  oval 4.5x3 hole 1.2 slot 3.2 at 0 deg: 0(3,3.72) 0(28,3.72)
  oct 1.2x1.8 hole 0.889: 1(21.04,0.88)
  oval 1.2x1.8 hole 0.889: 2(18.27,0.88) 3(15.5,0.88) 4(12.73,0.88) 5(9.96,0.88) 6(19.655,3.72) 7(16.885,3.72) 8(14.115,3.72) 9(11.345,3.72)
  silkscreen extent 0,0 31,14.8
DB25母 [mm]
  oval 4.6x3 hole 1.2 slot 3.2 at 0 deg: 0(3,2.9) 0(50,2.9)
  oval 1.2x1.8 hole 0.813: 1(9.88,1.515) 2(12.65,1.515) 3(15.42,1.515) 4(18.19,1.515) 5(20.96,1.515) 6(23.73,1.515) 7(26.5,1.515) 8(29.27,1.515) 9(32.04,1.515) 10(34.81,1.515) 11(37.58,1.515) 12(40.35,1.515) 13(43.12,1.515) 14(11.265,4.285) 15(14.035,4.285) 16(16.805,4.285) 17(19.575,4.285) 18(22.345,4.285) 19(25.115,4.285) 20(27.885,4.285) 21(30.655,4.285) 22(33.425,4.285) 23(36.195,4.285) 24(38.965,4.285) 25(41.735,4.285)
  silkscreen extent 0,0 53,18.4
DC5.5-DC007 [mm]
  round 2.8 hole 1.6: 1(5.3,0.7)
  oval 3.302x1.778 hole 0.8 slot 2 at 0 deg: 2(5.3,6.9)
  oval 1.778x3.302 hole 0.8 slot 2 at 90 deg: 3(0.3,7.4) 3(0.3,2.8) 3(10.3,7.4) 3(10.3,2.8)
  silkscreen extent 0,0 10.6,13.1
DO-214B(SMB) [mm]
  rect 1.8x2.4 smd: A(0,0) K(4.7,0)
  silkscreen extent 0,-1.8 4.6,1.8
IDC-2X32(2.54)B [mm]
  oval 1.8x1.2 hole 1: 1(-4.7,39.37) 2(-2.16,39.37) 3(-4.7,36.83) 4(-2.16,36.83) 5(-4.7,34.29) 6(-2.16,34.29) 7(-4.7,31.75) 8(-2.16,31.75) 9(-4.7,29.21) 10(-2.16,29.21) 11(-4.7,26.67) 12(-2.16,26.67) 13(-4.7,24.13) 14(-2.16,24.13) 15(-4.7,21.59) 16(-2.16,21.59) 17(-4.7,19.05) 18(-2.16,19.05) 19(-4.7,16.51) 20(-2.16,16.51) 21(-4.7,13.97) 22(-2.16,13.97) 23(-4.7,11.43) 24(-2.16,11.43) 25(-4.7,8.89) 26(-2.16,8.89) 27(-4.7,6.35) 28(-2.16,6.35) 29(-4.7,3.81) 30(-2.16,3.81) 31(-4.7,1.27) 32(-2.16,1.27) 33(-4.7,-1.27) 34(-2.16,-1.27) 35(-4.7,-3.81) 36(-2.16,-3.81) 37(-4.7,-6.35) 38(-2.16,-6.35) 39(-4.7,-8.89) 40(-2.16,-8.89) 41(-4.7,-11.43) 42(-2.16,-11.43) 43(-4.7,-13.97) 44(-2.16,-13.97) 45(-4.7,-16.51) 46(-2.16,-16.51) 47(-4.7,-19.05) 48(-2.16,-19.05) 49(-4.7,-21.59) 50(-2.16,-21.59) 51(-4.7,-24.13) 52(-2.16,-24.13) 53(-4.7,-26.67) 54(-2.16,-26.67) 55(-4.7,-29.21) 56(-2.16,-29.21) 57(-4.7,-31.75) 58(-2.16,-31.75) 59(-4.7,-34.29) 60(-2.16,-34.29) 61(-4.7,-36.83) 62(-2.16,-36.83) 63(-4.7,-39.37) 64(-2.16,-39.37)
  silkscreen extent 0,-44.5 8.8,44.5
JP2 [mil]
  rect 20x30 smd: 1(0,0) 2(31.5,0)
  silkscreen extent -20,-25 51,25
L0630 [mm]
  rect 2.2x3.2 smd: 1(0.5,3.3) 2(6.1,3.3)
  silkscreen extent 0,0 6.6,6.6
L1010 [mm] "33uH"
  rect 2.5x3.5 smd: 1(0,0) 2(9.4,0)
  silkscreen extent -0.5,-5.2 9.9,5.2
LED0603 [mm]
  rect 0.8x0.9 smd: 1(0,0) 2(1.7,0)
  silkscreen extent -0.68,-0.64 2.32,0.64
LQFP48 [mm] "LQFP, 48-Leads, Body 9.0x9.0mm (max), Pitch 0.50mm, IPC Medium Density"
  oval 1.65x0.3 smd: 1(-4.075,2.75) 2(-4.075,2.25) 3(-4.075,1.75) 4(-4.075,1.25) 5(-4.075,0.75) 6(-4.075,0.25) 7(-4.075,-0.25) 8(-4.075,-0.75) 9(-4.075,-1.25) 10(-4.075,-1.75) 11(-4.075,-2.25) 12(-4.075,-2.75) 25(4.075,-2.75) 26(4.075,-2.25) 27(4.075,-1.75) 28(4.075,-1.25) 29(4.075,-0.75) 30(4.075,-0.25) 31(4.075,0.25) 32(4.075,0.75) 33(4.075,1.25) 34(4.075,1.75) 35(4.075,2.25) 36(4.075,2.75)
  oval 0.3x1.65 smd: 13(-2.75,-4.075) 14(-2.25,-4.075) 15(-1.75,-4.075) 16(-1.25,-4.075) 17(-0.75,-4.075) 18(-0.25,-4.075) 19(0.25,-4.075) 20(0.75,-4.075) 21(1.25,-4.075) 22(1.75,-4.075) 23(2.25,-4.075) 24(2.75,-4.075) 37(2.75,4.075) 38(2.25,4.075) 39(1.75,4.075) 40(1.25,4.075) 41(0.75,4.075) 42(0.25,4.075) 43(-0.25,4.075) 44(-0.75,4.075) 45(-1.25,4.075) 46(-1.75,4.075) 47(-2.25,4.075) 48(-2.75,4.075)
  silkscreen extent -4.2,-2.85 2.85,3.57
M2.6 [mm]
  round 4.5 hole 2.6: 1(0,0)
M2.8D5.2 [mm]
  round 5.2 hole 2.8: 1(0,0)
PH2x5 [mm]
  oval 0.9x1.5 hole 0.8: 1(0,0) 2(0,2) 3(2,0) 4(2,2) 5(4,0) 6(4,2) 7(6,0) 8(6,2) 9(8,0) 10(8,2)
  silkscreen extent -1,-1 9,3
PH2x10 [mm]
  oval 1x1.5 hole 0.8: 1(0,0) 2(0,2) 3(2,0) 4(2,2) 5(4,0) 6(4,2) 7(6,0) 8(6,2) 9(8,0) 10(8,2) 11(10,0) 12(10,2) 13(12,0) 14(12,2) 15(14,0) 16(14,2) 17(16,0) 18(16,2) 19(18,0) 20(18,2)
  silkscreen extent -1,-1 19,3
PH2x22 [mm]
  oval 1x1.5 hole 0.8: 1(0,0) 2(0,2) 3(2,0) 4(2,2) 5(4,0) 6(4,2) 7(6,0) 8(6,2) 9(8,0) 10(8,2) 11(10,0) 12(10,2) 13(12,0) 14(12,2) 15(14,0) 16(14,2) 17(16,0) 18(16,2) 19(18,0) 20(18,2) 21(20,0) 22(20,2) 23(22,0) 24(22,2) 25(24,0) 26(24,2) 27(26,0) 28(26,2) 29(28,0) 30(28,2) 31(30,0) 32(30,2) 33(32,0) 34(32,2) 35(34,0) 36(34,2) 37(36,0) 38(36,2) 39(38,0) 40(38,2) 41(40,0) 42(40,2) 43(42,0) 44(42,2)
  silkscreen extent -1,-1 43,3
PH2x30 [mm]
  oval 1x1.5 hole 0.8: 1(0,0) 2(0,2) 3(2,0) 4(2,2) 5(4,0) 6(4,2) 7(6,0) 8(6,2) 9(8,0) 10(8,2) 11(10,0) 12(10,2) 13(12,0) 14(12,2) 15(14,0) 16(14,2) 17(16,0) 18(16,2) 19(18,0) 20(18,2) 21(20,0) 22(20,2) 23(22,0) 24(22,2) 25(24,0) 26(24,2) 27(26,0) 28(26,2) 29(28,0) 30(28,2) 31(30,0) 32(30,2) 33(32,0) 34(32,2) 35(34,0) 36(34,2) 37(36,0) 38(36,2) 39(38,0) 40(38,2) 41(40,0) 42(40,2) 43(42,0) 44(42,2) 45(44,0) 46(44,2) 47(46,0) 48(46,2) 49(48,0) 50(48,2) 51(50,0) 52(50,2) 53(52,0) 54(52,2) 55(54,0) 56(54,2) 57(56,0) 58(56,2) 59(58,0) 60(58,2)
  silkscreen extent -1,-1 59,3
PH2x40 [mm]
  oval 1x1.5 hole 0.8: 1(0,0) 2(0,2) 3(2,0) 4(2,2) 5(4,0) 6(4,2) 7(6,0) 8(6,2) 9(8,0) 10(8,2) 11(10,0) 12(10,2) 13(12,0) 14(12,2) 15(14,0) 16(14,2) 17(16,0) 18(16,2) 19(18,0) 20(18,2) 21(20,0) 22(20,2) 23(22,0) 24(22,2) 25(24,0) 26(24,2) 27(26,0) 28(26,2) 29(28,0) 30(28,2) 31(30,0) 32(30,2) 33(32,0) 34(32,2) 35(34,0) 36(34,2) 37(36,0) 38(36,2) 39(38,0) 40(38,2) 41(40,0) 42(40,2) 43(42,0) 44(42,2) 45(44,0) 46(44,2) 47(46,0) 48(46,2) 49(48,0) 50(48,2) 51(50,0) 52(50,2) 53(52,0) 54(52,2) 55(54,0) 56(54,2) 57(56,0) 58(56,2) 59(58,0) 60(58,2) 61(60,0) 62(60,2) 63(62,0) 64(62,2) 65(64,0) 66(64,2) 67(66,0) 68(66,2) 69(68,0) 70(68,2) 71(70,0) 72(70,2) 73(72,0) 74(72,2) 75(74,0) 76(74,2) 77(76,0) 78(76,2) 79(78,0) 80(78,2)
  silkscreen extent -1,-1 79,3
PH-2 [mm]
  oval 1x1.4 hole 0.7: 1(0,0) 2(2,0)
  silkscreen extent -2,-1.8 4,3
PH-8B [mm]
  oval 1x1.4 hole 0.7: 1(0,0) 2(2,0) 3(4,0) 4(6,0) 5(8,0) 6(10,0) 7(12,0) 8(14,0)
  silkscreen extent -2,0 16,6
PH-10B [mm]
  oval 1x1.4 hole 0.7: 1(0,0) 2(2,0) 3(4,0) 4(6,0) 5(8,0) 6(10,0) 7(12,0) 8(14,0) 9(16,0) 10(18,0)
  silkscreen extent -2,0 20,6
PLCC32P#1 [mm]
  oval 1.3x1.143 / inner round 1.3 / far side round 1.3 hole 0.7: 1(0,0) 2(-2.54,2.54) 3(-2.54,0) 4(-5.08,2.54) 5(-7.62,0) 6(-5.08,0) 7(-7.62,-2.54) 8(-5.08,-2.54) 9(-7.62,-5.08) 10(-5.08,-5.1) 11(-7.62,-7.62) 12(-5.08,-7.6) 13(-7.62,-10.16) 14(-5.08,-12.7) 15(-5.08,-10.16) 16(-2.54,-12.7) 17(-2.54,-10.16) 18(0,-12.7) 19(0,-10.16) 20(2.54,-12.7) 21(5.08,-10.16) 22(2.54,-10.16) 23(5.08,-7.62) 24(2.54,-7.62) 25(5.08,-5.08) 26(2.54,-5.08) 27(5.08,-2.54) 28(2.54,-2.54) 29(5.08,0) 30(2.54,2.54) 31(2.54,0) 32(0,2.54)
  silkscreen extent -10.08,-15.1 7.42,4.9
PLCC32P#2 [mm]
  oval 1.3x1.067 / inner round 1.3 / far side round 1.3 hole 0.7: 1(0,0) 2(-2.54,2.54) 3(-2.54,0) 4(-5.08,2.54) 5(-7.62,0) 6(-5.08,0) 7(-7.62,-2.54) 8(-5.08,-2.54) 9(-7.62,-5.08) 10(-5.08,-5.1) 11(-7.62,-7.62) 12(-5.08,-7.6) 13(-7.62,-10.16) 14(-5.08,-12.7) 15(-5.08,-10.16) 16(-2.54,-12.7) 17(-2.54,-10.16) 18(0,-12.7) 19(0,-10.16) 20(2.54,-12.7) 21(5.08,-10.16) 22(2.54,-10.16) 23(5.08,-7.62) 24(2.54,-7.62) 25(5.08,-5.08) 26(2.54,-5.08) 27(5.08,-2.54) 28(2.54,-2.54) 29(5.08,0) 30(2.54,2.54) 31(2.54,0) 32(0,2.54)
  silkscreen extent -10.08,-15.1 7.42,4.9
PQFP100B [mm]
  rect 0.26x2 smd: 1(0,0) 2(0.65,0) 3(1.3,0) 4(1.95,0) 5(2.6,0) 6(3.25,0) 7(3.9,0) 8(4.55,0) 9(5.2,0) 10(5.85,0) 11(6.5,0) 12(7.15,0) 13(7.8,0) 14(8.45,0) 15(9.1,0) 16(9.75,0) 17(10.4,0) 18(11.05,0) 19(11.7,0) 20(12.35,0) 21(13,0) 22(13.65,0) 23(14.3,0) 24(14.95,0) 25(15.6,0) 26(16.25,0) 27(16.9,0) 28(17.55,0) 29(18.2,0) 30(18.85,0) 51(18.85,18.2) 52(18.2,18.2) 53(17.55,18.2) 54(16.9,18.2) 55(16.25,18.2) 56(15.6,18.2) 57(14.95,18.2) 58(14.3,18.2) 59(13.65,18.2) 60(13,18.2) 61(12.35,18.2) 62(11.7,18.2) 63(11.05,18.2) 64(10.4,18.2) 65(9.75,18.2) 66(9.1,18.2) 67(8.45,18.2) 68(7.8,18.2) 69(7.15,18.2) 70(6.5,18.2) 71(5.85,18.2) 72(5.2,18.2) 73(4.55,18.2) 74(3.9,18.2) 75(3.25,18.2) 76(2.6,18.2) 77(1.95,18.2) 78(1.3,18.2) 79(0.65,18.2) 80(0,18.2)
  rect 2x0.26 smd: 31(21.775,2.925) 32(21.775,3.575) 33(21.775,4.225) 34(21.775,4.875) 35(21.775,5.525) 36(21.775,6.175) 37(21.775,6.825) 38(21.775,7.475) 39(21.775,8.125) 40(21.775,8.775) 41(21.775,9.425) 42(21.775,10.075) 43(21.775,10.725) 44(21.775,11.375) 45(21.775,12.025) 46(21.775,12.675) 47(21.775,13.325) 48(21.775,13.975) 49(21.775,14.625) 50(21.775,15.275) 81(-2.925,15.275) 82(-2.925,14.625) 83(-2.925,13.975) 84(-2.925,13.325) 85(-2.925,12.675) 86(-2.925,12.025) 87(-2.925,11.375) 88(-2.925,10.725) 89(-2.925,10.075) 90(-2.925,9.425) 91(-2.925,8.775) 92(-2.925,8.125) 93(-2.925,7.475) 94(-2.925,6.825) 95(-2.925,6.175) 96(-2.925,5.525) 97(-2.925,4.875) 98(-2.925,4.225) 99(-2.925,3.575) 100(-2.925,2.925)
  silkscreen extent -3.81,-0.76 22.61,19.05
PS2 [mm]
  round 1.6 hole 1: 1(-4.4,5.7) 2(-4.4,8.5) 3(-4.4,3.7) 4(-4.4,10.5) 5(-2,3.7) 6(-2,10.5)
  oval 2.5x3.8 hole 1.2 slot 2.5 at 90 deg: 7(-8.7,7.1)
  oval 3.5x2.5 hole 1.2 slot 2.2 at 0 deg: 7(-7.6,14.2) 7(-7.6,0)
  silkscreen extent -13.2,0 0,14.2
QFP208 [mm]
  oval 0.3x1.8 smd: 1(0,0) 2(0.5,0) 3(1,0) 4(1.5,0) 5(2,0) 6(2.5,0) 7(3,0) 8(3.5,0) 9(4,0) 10(4.5,0) 11(5,0) 12(5.5,0) 13(6,0) 14(6.5,0) 15(7,0) 16(7.5,0) 17(8,0) 18(8.5,0) 19(9,0) 20(9.5,0) 21(10,0) 22(10.5,0) 23(11,0) 24(11.5,0) 25(12,0) 26(12.5,0) 27(13,0) 28(13.5,0) 29(14,0) 30(14.5,0) 31(15,0) 32(15.5,0) 33(16,0) 34(16.5,0) 35(17,0) 36(17.5,0) 37(18,0) 38(18.5,0) 39(19,0) 40(19.5,0) 41(20,0) 42(20.5,0) 43(21,0) 44(21.5,0) 45(22,0) 46(22.5,0) 47(23,0) 48(23.5,0) 49(24,0) 50(24.5,0) 51(25,0) 52(25.5,0) 105(25.5,30.788) 106(25,30.788) 107(24.5,30.788) 108(24,30.788) 109(23.5,30.788) 110(23,30.788) 111(22.5,30.788) 112(22,30.788) 113(21.5,30.788) 114(21,30.788) 115(20.5,30.788) 116(20,30.788) 117(19.5,30.788) 118(19,30.788) 119(18.5,30.788) 120(18,30.788) 121(17.5,30.788) 122(17,30.788) 123(16.5,30.788) 124(16,30.788) 125(15.5,30.788) 126(15,30.788) 127(14.5,30.788) 128(14,30.788) 129(13.5,30.788) 130(13,30.788) 131(12.5,30.788) 132(12,30.788) 133(11.5,30.788) 134(11,30.788) 135(10.5,30.788) 136(10,30.788) 137(9.5,30.788) 138(9,30.788) 139(8.5,30.788) 140(8,30.788) 141(7.5,30.788) 142(7,30.788) 143(6.5,30.788) 144(6,30.788) 145(5.5,30.788) 146(5,30.788) 147(4.5,30.788) 148(4,30.788) 149(3.5,30.788) 150(3,30.788) 151(2.5,30.788) 152(2,30.788) 153(1.5,30.788) 154(1,30.788) 155(0.5,30.788) 156(0,30.788)
  oval 1.8x0.3 smd: 53(28.158,2.658) 54(28.158,3.158) 55(28.158,3.658) 56(28.158,4.158) 57(28.158,4.658) 58(28.158,5.158) 59(28.158,5.658) 60(28.158,6.158) 61(28.158,6.658) 62(28.158,7.158) 63(28.158,7.658) 64(28.158,8.158) 65(28.158,8.658) 66(28.158,9.158) 67(28.158,9.658) 68(28.158,10.158) 69(28.158,10.658) 70(28.158,11.158) 71(28.158,11.658) 72(28.158,12.158) 73(28.158,12.658) 74(28.158,13.158) 75(28.158,13.658) 76(28.158,14.158) 77(28.158,14.658) 78(28.158,15.158) 79(28.158,15.658) 80(28.158,16.158) 81(28.158,16.658) 82(28.158,17.158) 83(28.158,17.658) 84(28.158,18.158) 85(28.158,18.658) 86(28.158,19.158) 87(28.158,19.658) 88(28.158,20.158) 89(28.158,20.658) 90(28.158,21.158) 91(28.158,21.658) 92(28.158,22.158) 93(28.158,22.658) 94(28.158,23.158) 95(28.158,23.658) 96(28.158,24.158) 97(28.158,24.658) 98(28.158,25.158) 99(28.158,25.658) 100(28.158,26.158) 101(28.158,26.658) 102(28.158,27.158) 103(28.158,27.658) 104(28.158,28.158) 157(-2.658,28.158) 158(-2.658,27.658) 159(-2.658,27.158) 160(-2.658,26.658) 161(-2.658,26.158) 162(-2.658,25.658) 163(-2.658,25.158) 164(-2.658,24.658) 165(-2.658,24.158) 166(-2.658,23.658) 167(-2.658,23.158) 168(-2.658,22.658) 169(-2.658,22.158) 170(-2.658,21.658) 171(-2.658,21.158) 172(-2.658,20.658) 173(-2.658,20.158) 174(-2.658,19.658) 175(-2.658,19.158) 176(-2.658,18.658) 177(-2.658,18.158) 178(-2.658,17.658) 179(-2.658,17.158) 180(-2.658,16.658) 181(-2.658,16.158) 182(-2.658,15.658) 183(-2.658,15.158) 184(-2.658,14.658) 185(-2.658,14.158) 186(-2.658,13.658) 187(-2.658,13.158) 188(-2.658,12.658) 189(-2.658,12.158) 190(-2.658,11.658) 191(-2.658,11.158) 192(-2.658,10.658) 193(-2.658,10.158) 194(-2.658,9.658) 195(-2.658,9.158) 196(-2.658,8.658) 197(-2.658,8.158) 198(-2.658,7.658) 199(-2.658,7.158) 200(-2.658,6.658) 201(-2.658,6.158) 202(-2.658,5.658) 203(-2.658,5.158) 204(-2.658,4.658) 205(-2.658,4.158) 206(-2.658,3.658) 207(-2.658,3.158) 208(-2.658,2.658)
  silkscreen extent -3.3,-1.84 28.7,31.4
R0603 [mil]
  rect 38x35 smd: 1(0,0) 2(66.93,0)
  silkscreen extent -26,-24 93,24
SMD-EC-F8 [mm]
  rect 3x1.4 smd: 1(-3.8,0) 2(3.8,0)
  silkscreen extent -4.2,-4.2 4.2,4.2
SO-8 [mil]
  rect 80x24 smd: 1(0,0)
  oval 80x24 smd: 2(0,-50) 3(0,-100) 4(0,-150) 5(220,-150) 6(220,-100) 7(220,-50) 8(220,0)
  silkscreen extent 60,-175 160,25
"SO-8 A" [mil]
  rect 78.74x157.48 smd: 0(110,-75)
  rect 80x24 smd: 1(0,0)
  oval 80x24 smd: 2(0,-50) 3(0,-100) 4(0,-150) 5(220,-150) 6(220,-100) 7(220,-50) 8(220,0)
  silkscreen extent 60,-175 160,25
SO-16 [mil]
  oval 80x22 smd: 1(0,0) 2(0,-50) 3(0,-100) 4(0,-150) 5(0,-200) 6(0,-250) 7(0,-300) 8(0,-350) 9(220,-350) 10(220,-300) 11(220,-250) 12(220,-200) 13(220,-150) 14(220,-100) 15(220,-50) 16(220,0)
  silkscreen extent 60,-375 160,25
SOD123 [mm]
  rect 1x1 smd: A(0,0) K(3.6,0)
  silkscreen extent 0.69,-0.9 2.93,0.9
SOJ-24-A [mil] "薄贴片"
  oval 80x24 smd: 1(0,0) 2(0,-50) 3(0,-100) 4(0,-150) 5(0,-200) 6(0,-250) 7(0,-350) 8(0,-400) 9(0,-450) 10(0,-500) 11(0,-550) 12(0,-600) 13(340,-600) 14(340,-550) 15(340,-500) 16(340,-450) 17(340,-400) 18(340,-350) 19(340,-250) 20(340,-200) 21(340,-150) 22(340,-100) 23(340,-50) 24(340,0)
  silkscreen extent 60,-625 280,25
SOP-28 [mm]
  oval 0.635x1.9 smd: 1(0,0) 2(1.27,0) 3(2.54,0) 4(3.81,0) 5(5.08,0) 6(6.35,0) 7(7.62,0) 8(8.89,0) 9(10.16,0) 10(11.43,0) 11(12.7,0) 12(13.97,0) 13(15.24,0) 14(16.51,0) 15(16.51,10) 16(15.24,10) 17(13.97,10) 18(12.7,10) 19(11.43,10) 20(10.16,10) 21(8.89,10) 22(7.62,10) 23(6.35,10) 24(5.08,10) 25(3.81,10) 26(2.54,10) 27(1.27,10) 28(0,10)
  silkscreen extent -1.14,0.41 17.27,8.8
SOT23 [mil]
  rect 36x36 smd: B(-37.5,-40) E(37.5,-40)
  rect 36x50 smd: C(0.5,40)
  silkscreen extent -58,-45 58,45
SOT23-5 [mm]
  rect 0.55x1.45 smd: 1(0,0) 2(0.95,0) 3(1.9,0) 4(1.9,2.15) 5(0,2.15)
  silkscreen extent -0.72,-1.15 2.5,1.98
SOT-23 [mil]
  rect 36x36 smd: 1(0,0) 2(75,0)
  rect 36x50 smd: 3(38,80)
  silkscreen extent -20,-5 95,85
SSOP28 [mm]
  rect 1.6x0.4 smd: 1(0,0) 2(0,-0.65) 3(0,-1.3) 4(0,-1.95) 5(0,-2.6) 6(0,-3.25) 7(0,-3.9) 8(0,-4.55) 9(0,-5.2) 10(0,-5.85) 11(0,-6.5) 12(0,-7.15) 13(0,-7.8) 14(0,-8.45) 15(7.8,-8.45) 16(7.8,-7.8) 17(7.8,-7.15) 18(7.8,-6.5) 19(7.8,-5.85) 20(7.8,-5.2) 21(7.8,-4.55) 22(7.8,-3.9) 23(7.8,-3.25) 24(7.8,-2.6) 25(7.8,-1.95) 26(7.8,-1.3) 27(7.8,-0.65) 28(7.8,0)
  silkscreen extent -0.1,-9.5 6.5,1
SW3 [mm]
  oval 1.4x2 hole 0.6 slot 1.1 at 90 deg: 0(0.3,1.3)
  oval 2x1.4 hole 0.6 slot 1 at 0 deg: 0(12.2,5)
  oval 1.016x1.4 hole 0.8: 1(8.5,2.6) 2(6,2.6) 3(3.5,2.6)
  silkscreen extent 0,-0.5 25.4,5.7
TO-252(DPAK) [mm] "D2-PAK/TO-263-AB; 3 Leads (1 Cropped); Body 15.5 (inc. leads) x 10.5 mm (LxW max)"
  rect 1.6x3.2 smd: 1(0,0) 3(4.6,0)
  rect 7x6 smd: 2(2.3,6.8)
  silkscreen extent -1.4,3 6,10
TO-252-MOS [mm] "D2-PAK/TO-263-AB; 3 Leads (1 Cropped); Body 15.5 (inc. leads) x 10.5 mm (LxW max)"
  rect 1.6x3.2 smd: 1(0,0) 2(4.6,0)
  rect 7x6 smd: 3(2.3,6.8)
  silkscreen extent -1.4,3 6,10
TO-263(T) [mil]
  rect 420x350 smd: 0(133,375)
  rect 42x140 smd: 1(0,0) 2(68,0) 3(134,0) 4(199,0) 5(266,0)
  silkscreen extent -77,177 343,555
USB-A-02 [mm]
  oval 3.2x1.4 hole 0.4 slot 2.1 at 0 deg: 0(3.4,13.1) 0(3.4,0.1)
  round 1.6 hole 0.8: D+(0.9,7.6) D-(0.9,5.6) GND(0.9,10.14) VCC(0.9,3.06)
  silkscreen extent 0,0 13.7,13.2
"VGA 15-S" [mil]
  oval 196.85x118.11 hole 47.24 slot 137.8 at 0 deg: 0(118.11,155.12) 0(1102.36,155.12)
  rect 60x60 hole 40: 1(429.92,77.17)
  round 60 hole 40: 2(520.08,77.17) 3(610.24,77.17) 4(700.39,77.17) 5(790.55,77.17) 6(384.84,155.12) 7(475,155.12) 8(565.16,155.12) 9(655.31,155.12) 10(745.47,155.12) 11(429.92,233.07) 12(520.08,233.07) 13(610.24,233.07) 14(700.39,233.07) 15(790.55,233.07)
  silkscreen extent 0,0 1220,583
XH2.54A-4 [mm]
  oval 1.1x1.651 hole 1: 1(0,0) 2(2.54,0) 3(5.08,0) 4(7.62,0)
  silkscreen extent -2.49,0.6 10.11,7.4

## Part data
C1 C2 C3 C4 C5 C6 C7 C8 C9 C15 C16 C17 C18 C19 C21 C24 C28 C29 C30 C31 C32 C36 C37 C38 C39 C40 C41 C42 C43 C44 C45 C46 C47 C48 C49 C50 C51 C52 C53 C54 C55 C56 C57 C58 C59 C60 C61 C62 C63 C64 C65 C66 C67 C68 C69 C70 C71 C72 C73 C74 C75 C76 C79 C80 C81 C82 C83 C84 C85 C99 C117 C118 C119 C120 C121 C122 C123 C124 C125 C126 C130 C131 C132 C133 C134 C135 C136 C137 C138 C139 C140 C141 C142 C143 C144 C145 C146 C147 C148 C149 CM1 CM2 CM3 CM4 CM5 CM6 CM7 CM8 CM9 CM10 CM11 CM12 CP1: library part 0CAP
C10 C11 C12 C13 C14 C20 C22 C23 C25 C26 C27 C33 C34 C35 C77 C78 C90 C91 C100 C101 C102 C103 C104 C105 C106 C107 C108 C109 C110 C111 C112 C113 C114 C115 C116 CN1 CN2 CN3 CN4 CN5: library part CAP
CP2 CP3 CP4 CP5 CP6 CP7 CP8 CP9 CP10 CP11 CP12: library part 0CAP1
D1 DP3 DP4 DP5 DP6 DP7 DP8 DP9 DP10: library part 0DIODE
DP1 DP2: library part DIODE1
L1 LP1 LP2: library part L
LED2: library part 0LED
LS1: "Loudspeaker"
P1 P2: library part CON7
P12: library part DB-VGA
PP1: "Connector"
Q1 Q3 Q8 Q9: library part 0NPN
Q2: library part 0PNP
Q4 Q5 Q6: library part MOS-SO-8
Q7: library part MOSFET-P, "P-Channel MOSFET", PackageDocument=1995/1996
R1 R3 R4 R5 R6 R7 R8 R9 R11 R12 R13 R14 R15 R16 R19 R20 R21 R22 R23 R24 R25 R26 R27 R28 R29 R30 R31 R32 R33 R34 R35 R36 R37 R38 R39 R40 R41 R42 R43 R44 R45 R46 R47 R48 R49 R50 R51 R52 R53 R54 R55 R56 R57 R58 R59 R60 R61 R62 R63 R64 R65 R66 R67 R68 R69 R70 R71 R72 R73 R74 R75 R76 R77 R78 R79 R80 R81 R82 R83 R84 R85 R86 R87 R88 R89 R90 R93 R94 R95 R96 R97 R99 R100 R101 R102 R103 R109 R118 R119 RM1 RM2 RM3 RM4 RM5 RM6 RM7 RM8 RM9 RM10 RM11 RM12 RM13 RM14 RM15 RM16 RM17 RM18 RM19 RM20 RM21 RM22 RM23 RM24 RM25 RP3 RP4: library part 0RES
R2 R92 R104 R105 R106 R107 R108 R110 R111 R112 R113 R114 R115 R116 R117 R120 R121 R122 R123 R124 R125 R126 R127 R128 R129 R130 R131 R132 R133 R134 R135 R136 R137 R138 R139 R140 R141 R142 R143 R144 R145 R146 R147 R150 R151 R152 RN3 RN4 RP1 RP2 RP6 RT1: library part RES2
SP1: library part SW1_1
U9: library part CH375
U18 U19: library part 74LS139
UP2: library part XL4016
UP4 UP5: library part LPW5209
UP6: library part LM79XX
USB1: library part USB_A
X1 X2: library part CRYSTAL-4P
X3 X4 X5 X6: library part CRYSTAL

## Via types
v1: diameter 0.508, hole 0.305, Top Layer to Bottom Layer, tented both sides, 1451 vias
v2: diameter 0.508, hole 0.3, Top Layer to Bottom Layer, 67 vias
v3: diameter 1.2, hole 1.2, Top Layer to Bottom Layer, 2 vias

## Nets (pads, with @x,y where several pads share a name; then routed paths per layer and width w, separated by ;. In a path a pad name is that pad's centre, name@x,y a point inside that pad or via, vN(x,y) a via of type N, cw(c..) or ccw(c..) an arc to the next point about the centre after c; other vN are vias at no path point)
0WS#: P5.15 P10.15 P11.15 R27.1 U1.165 | length 275.4
  Top Layer w0.203: P5.15@40.01,133.9 40.01,134.2 38.797,135.413 38.797,139.995 39.469,140.667 107.645,140.667 118.553,129.759 123.221,129.759 123.867,130.405 128.546,130.405 131.507,133.366 139.581,133.366 v1(140.192,132.755) ; U1.165@178.463,80.836 185.911,80.836 186.168,81.092 191.172,81.092 191.857,81.778 v1(193.737,81.778)
  Bottom Layer w0.203: R27.1@38.772,138.7 38.772,135.438 40.01,134.2 P5.15@40.01,133.9 ; v1(140.192,132.755) 140.245,132.807 166.381,132.807 189.573,109.615 189.573,100.701 193.738,96.536 v1(193.737,81.778) 193.738,63.006 202.542,54.202 213.286,54.202 215.5,51.989 P10.15@215.5,51 ; P11.15@215.384,46.116 215.384,46.865 214.558,47.691 214.558,49.622 P10.15@215.5,50.564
